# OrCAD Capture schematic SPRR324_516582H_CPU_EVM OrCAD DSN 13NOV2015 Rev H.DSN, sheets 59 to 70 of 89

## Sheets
59 SH66 - ETHERNET LEDS: rev: A
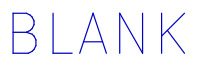
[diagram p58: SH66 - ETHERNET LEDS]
60 SH67 - APPLICATION IF CONN1: size B; rev: A
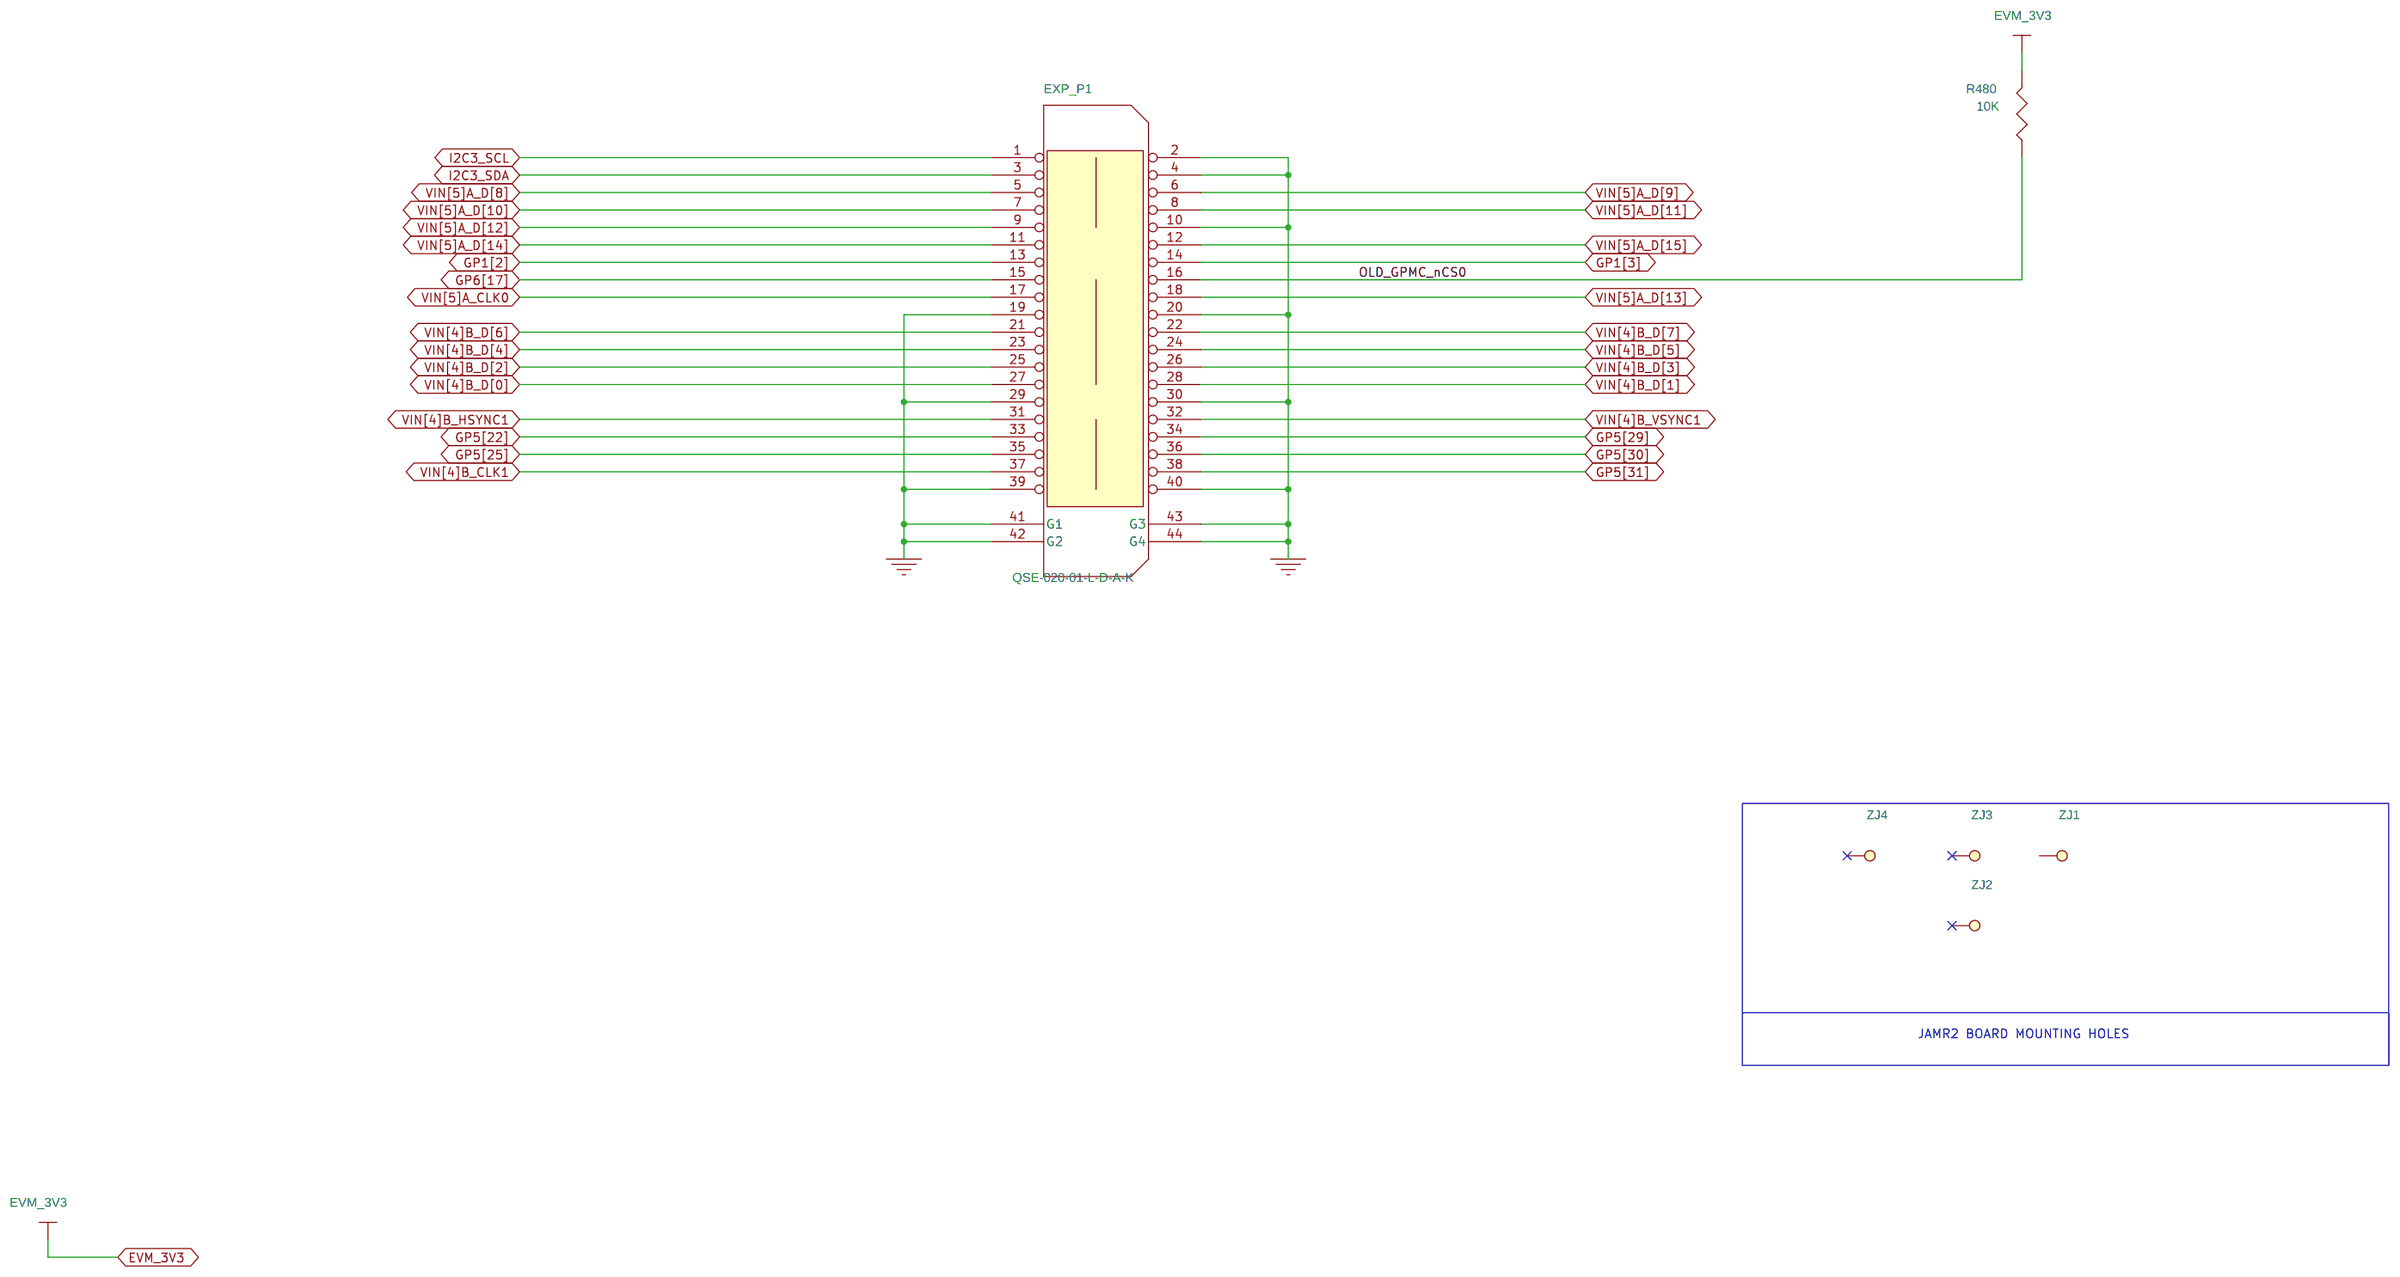
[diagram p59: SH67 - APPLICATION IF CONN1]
61 SH68 - APPLICATION IF  CONN2: size B; rev: A
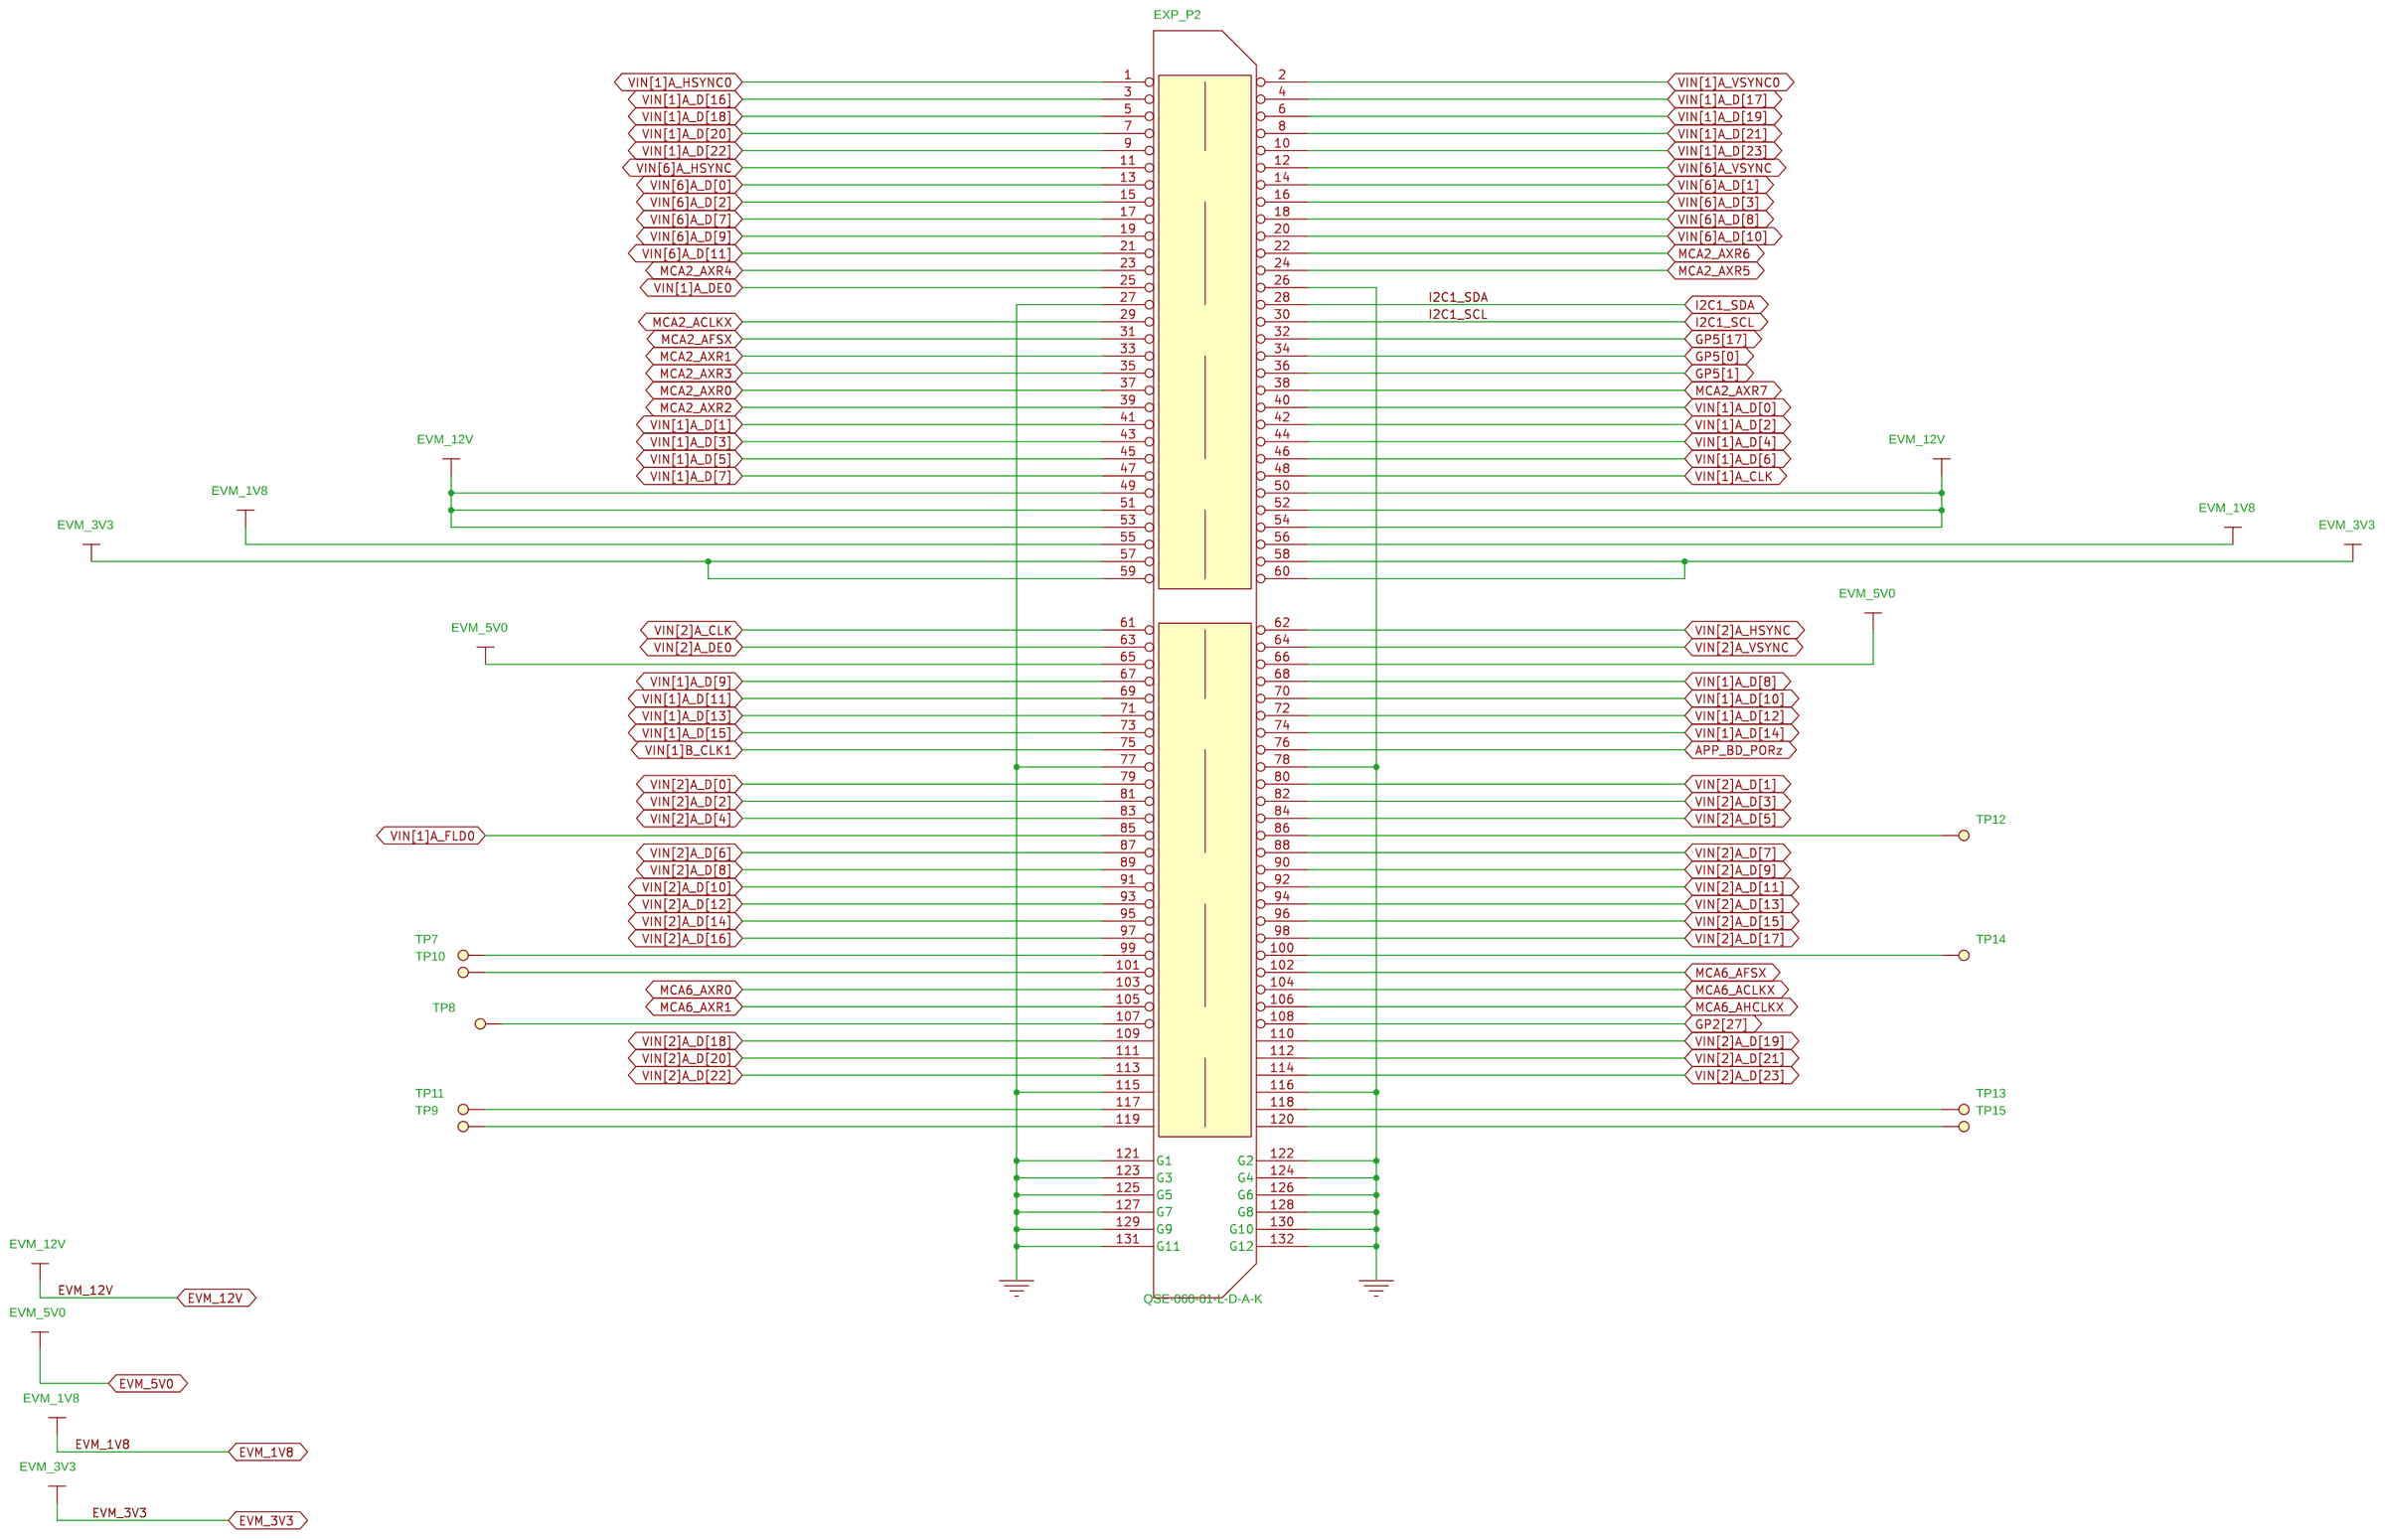
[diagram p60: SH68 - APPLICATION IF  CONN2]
62 SH69 - APPLICATION IF  CONN3: size B; rev: A
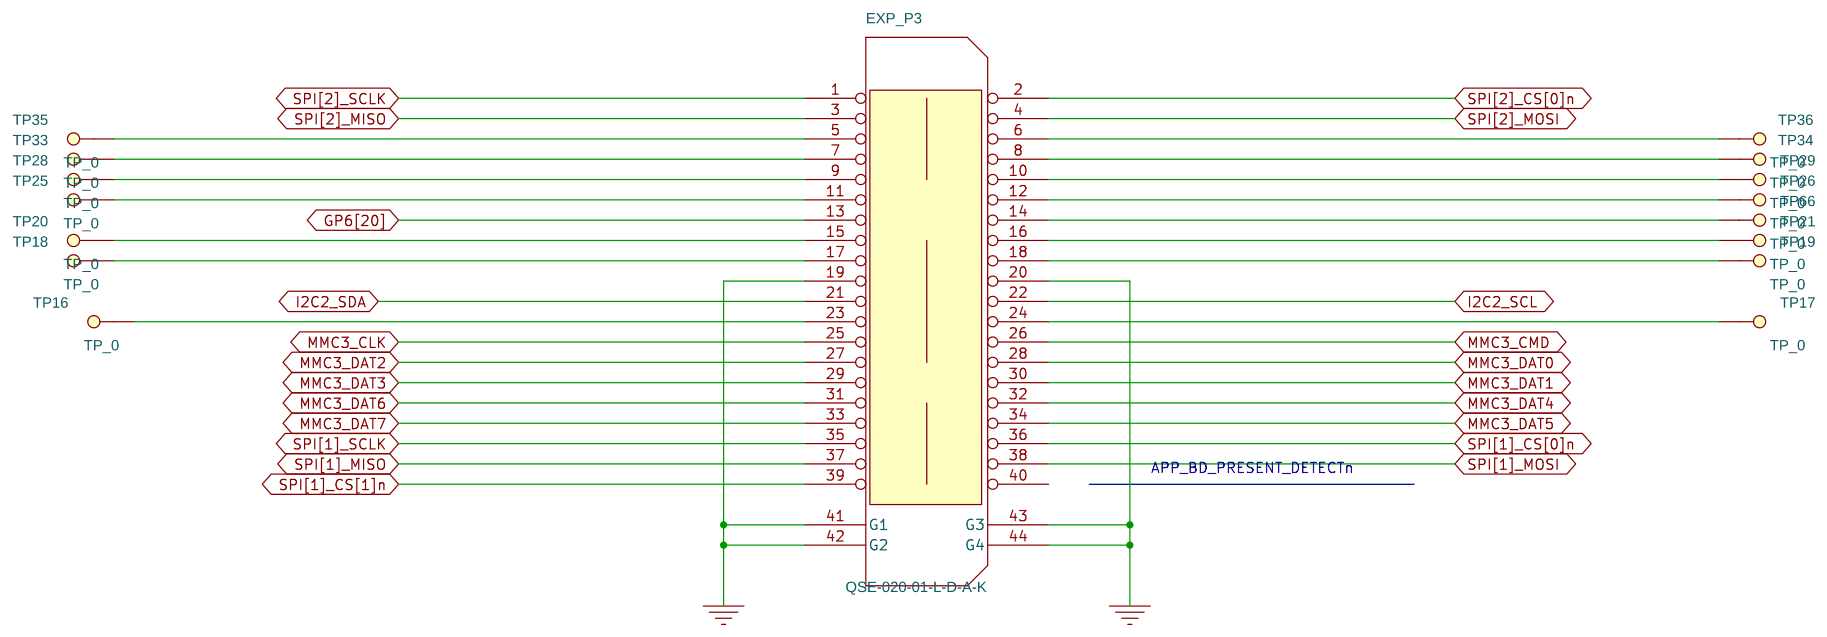
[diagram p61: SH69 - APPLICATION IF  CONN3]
63 SH70 - PMIC CONTROL: size B; rev: G3
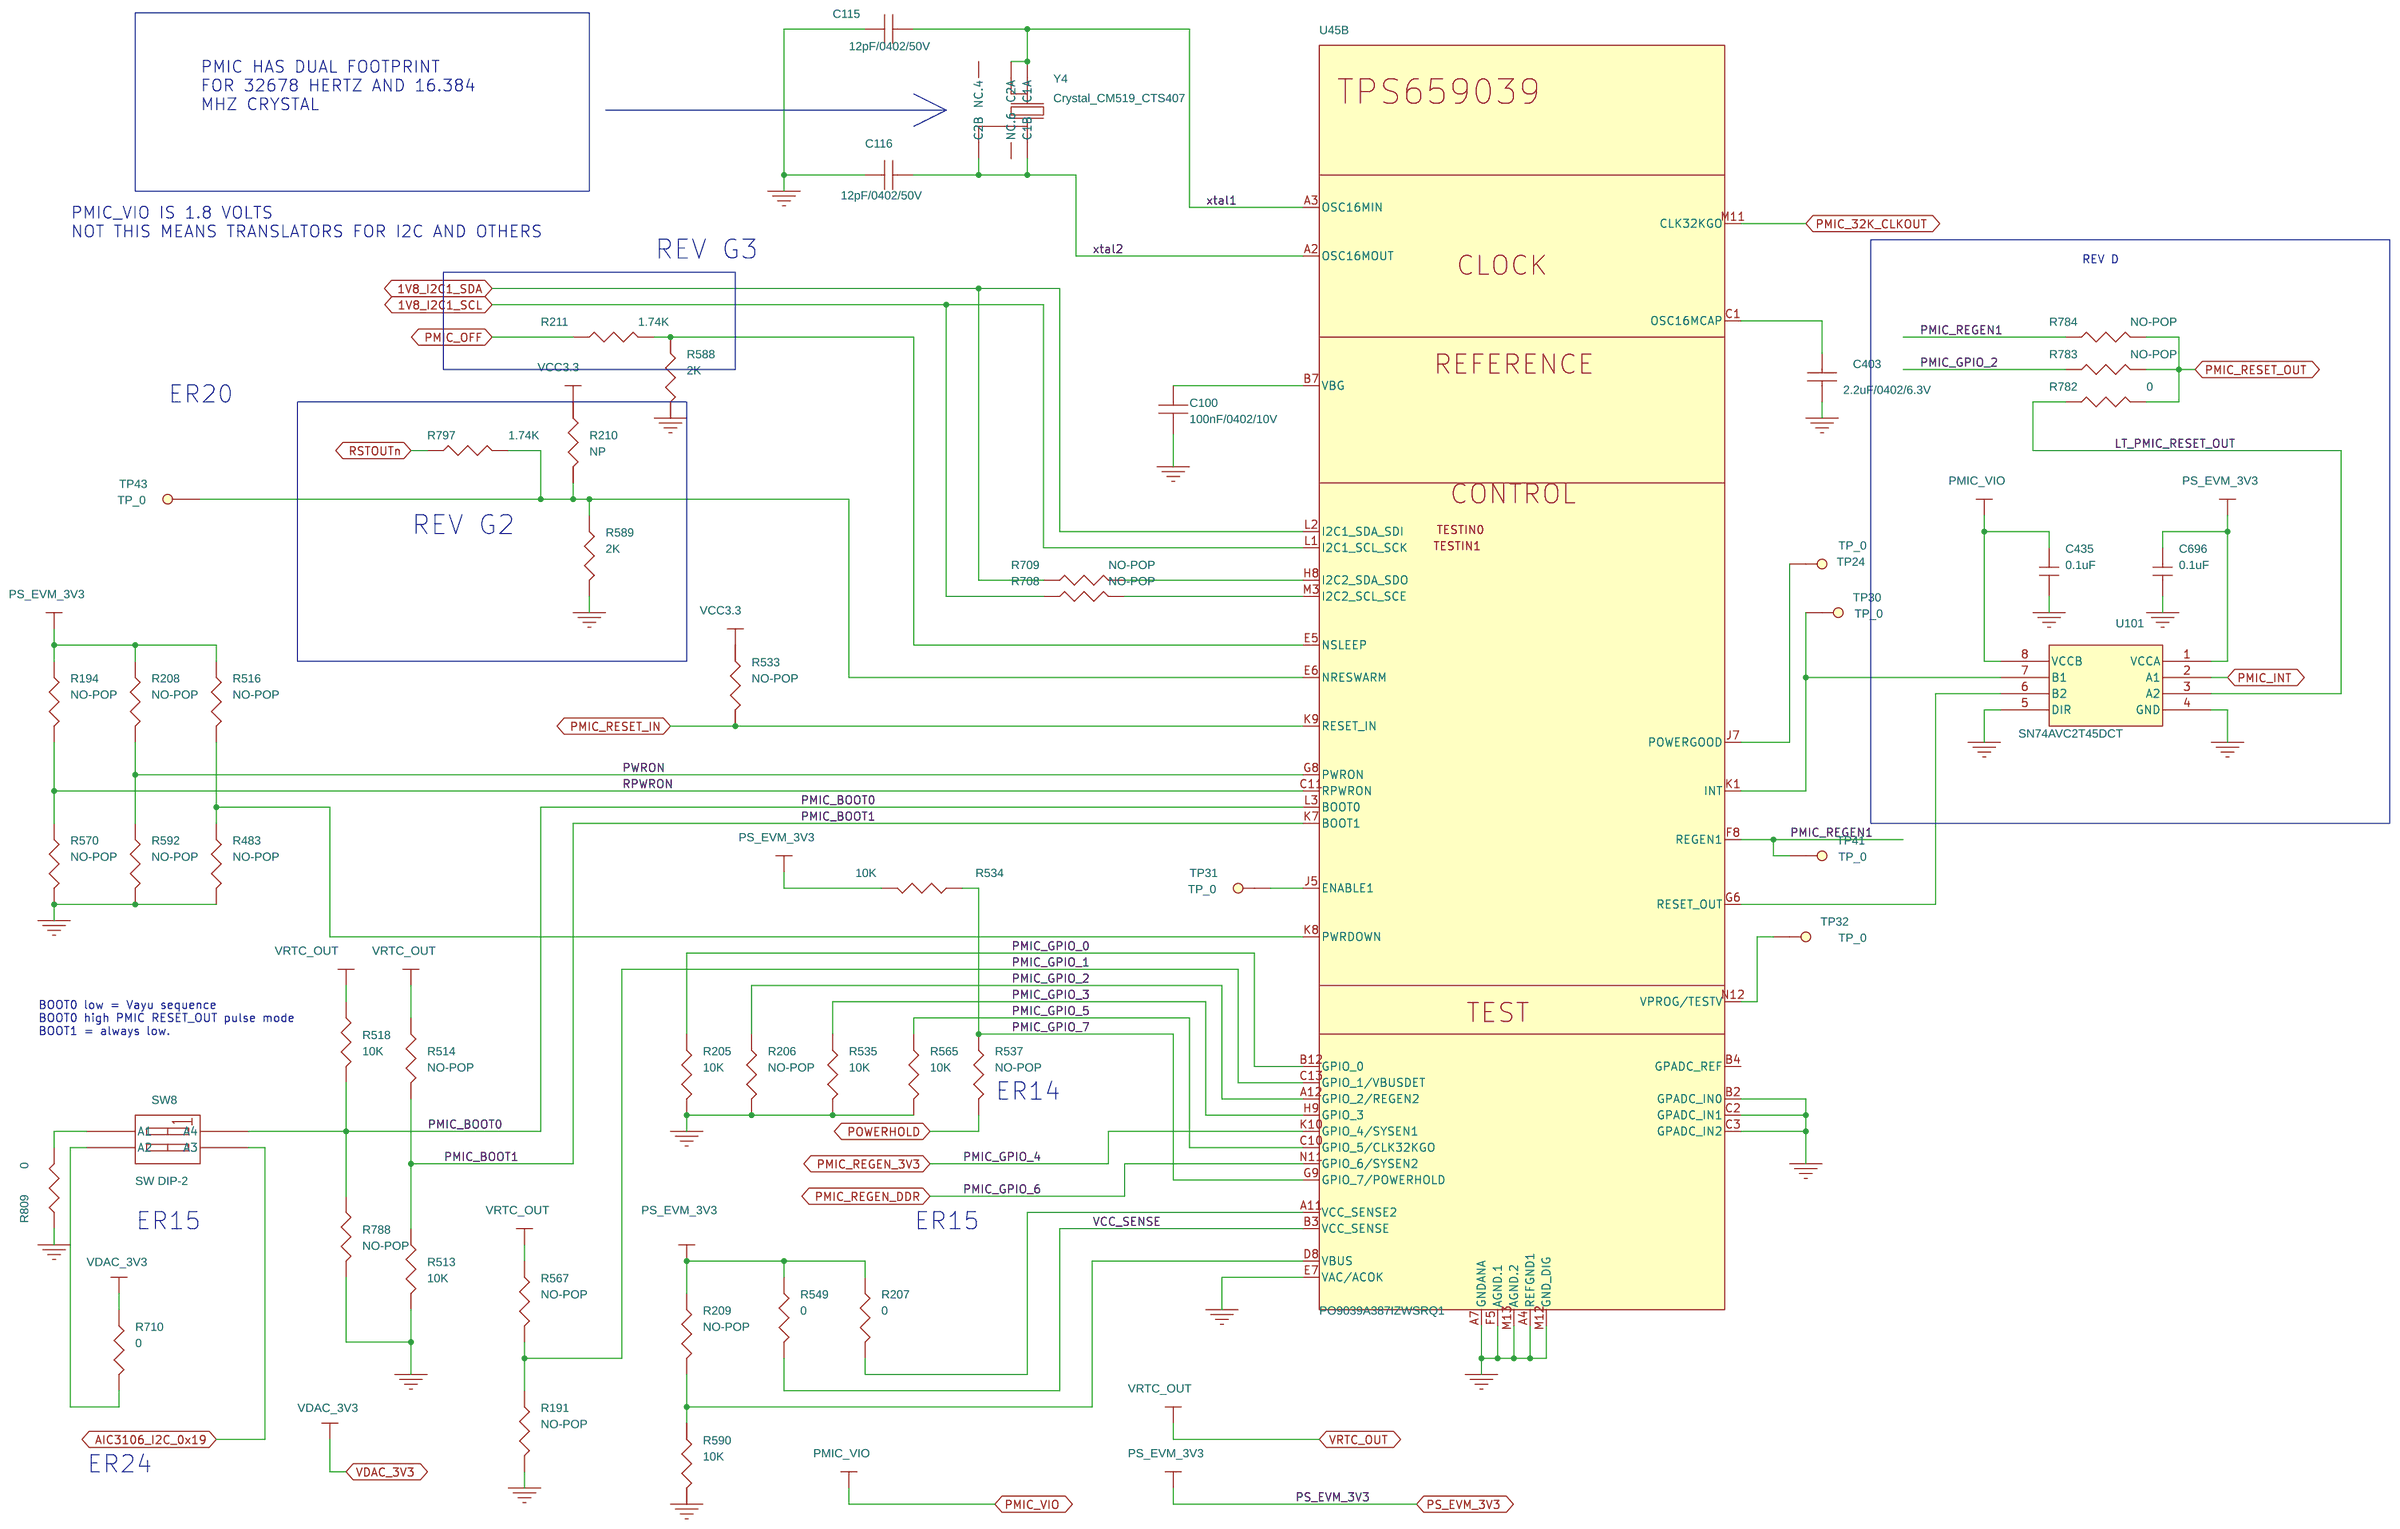
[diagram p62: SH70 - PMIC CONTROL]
64 SH71 - PMIC2: size B
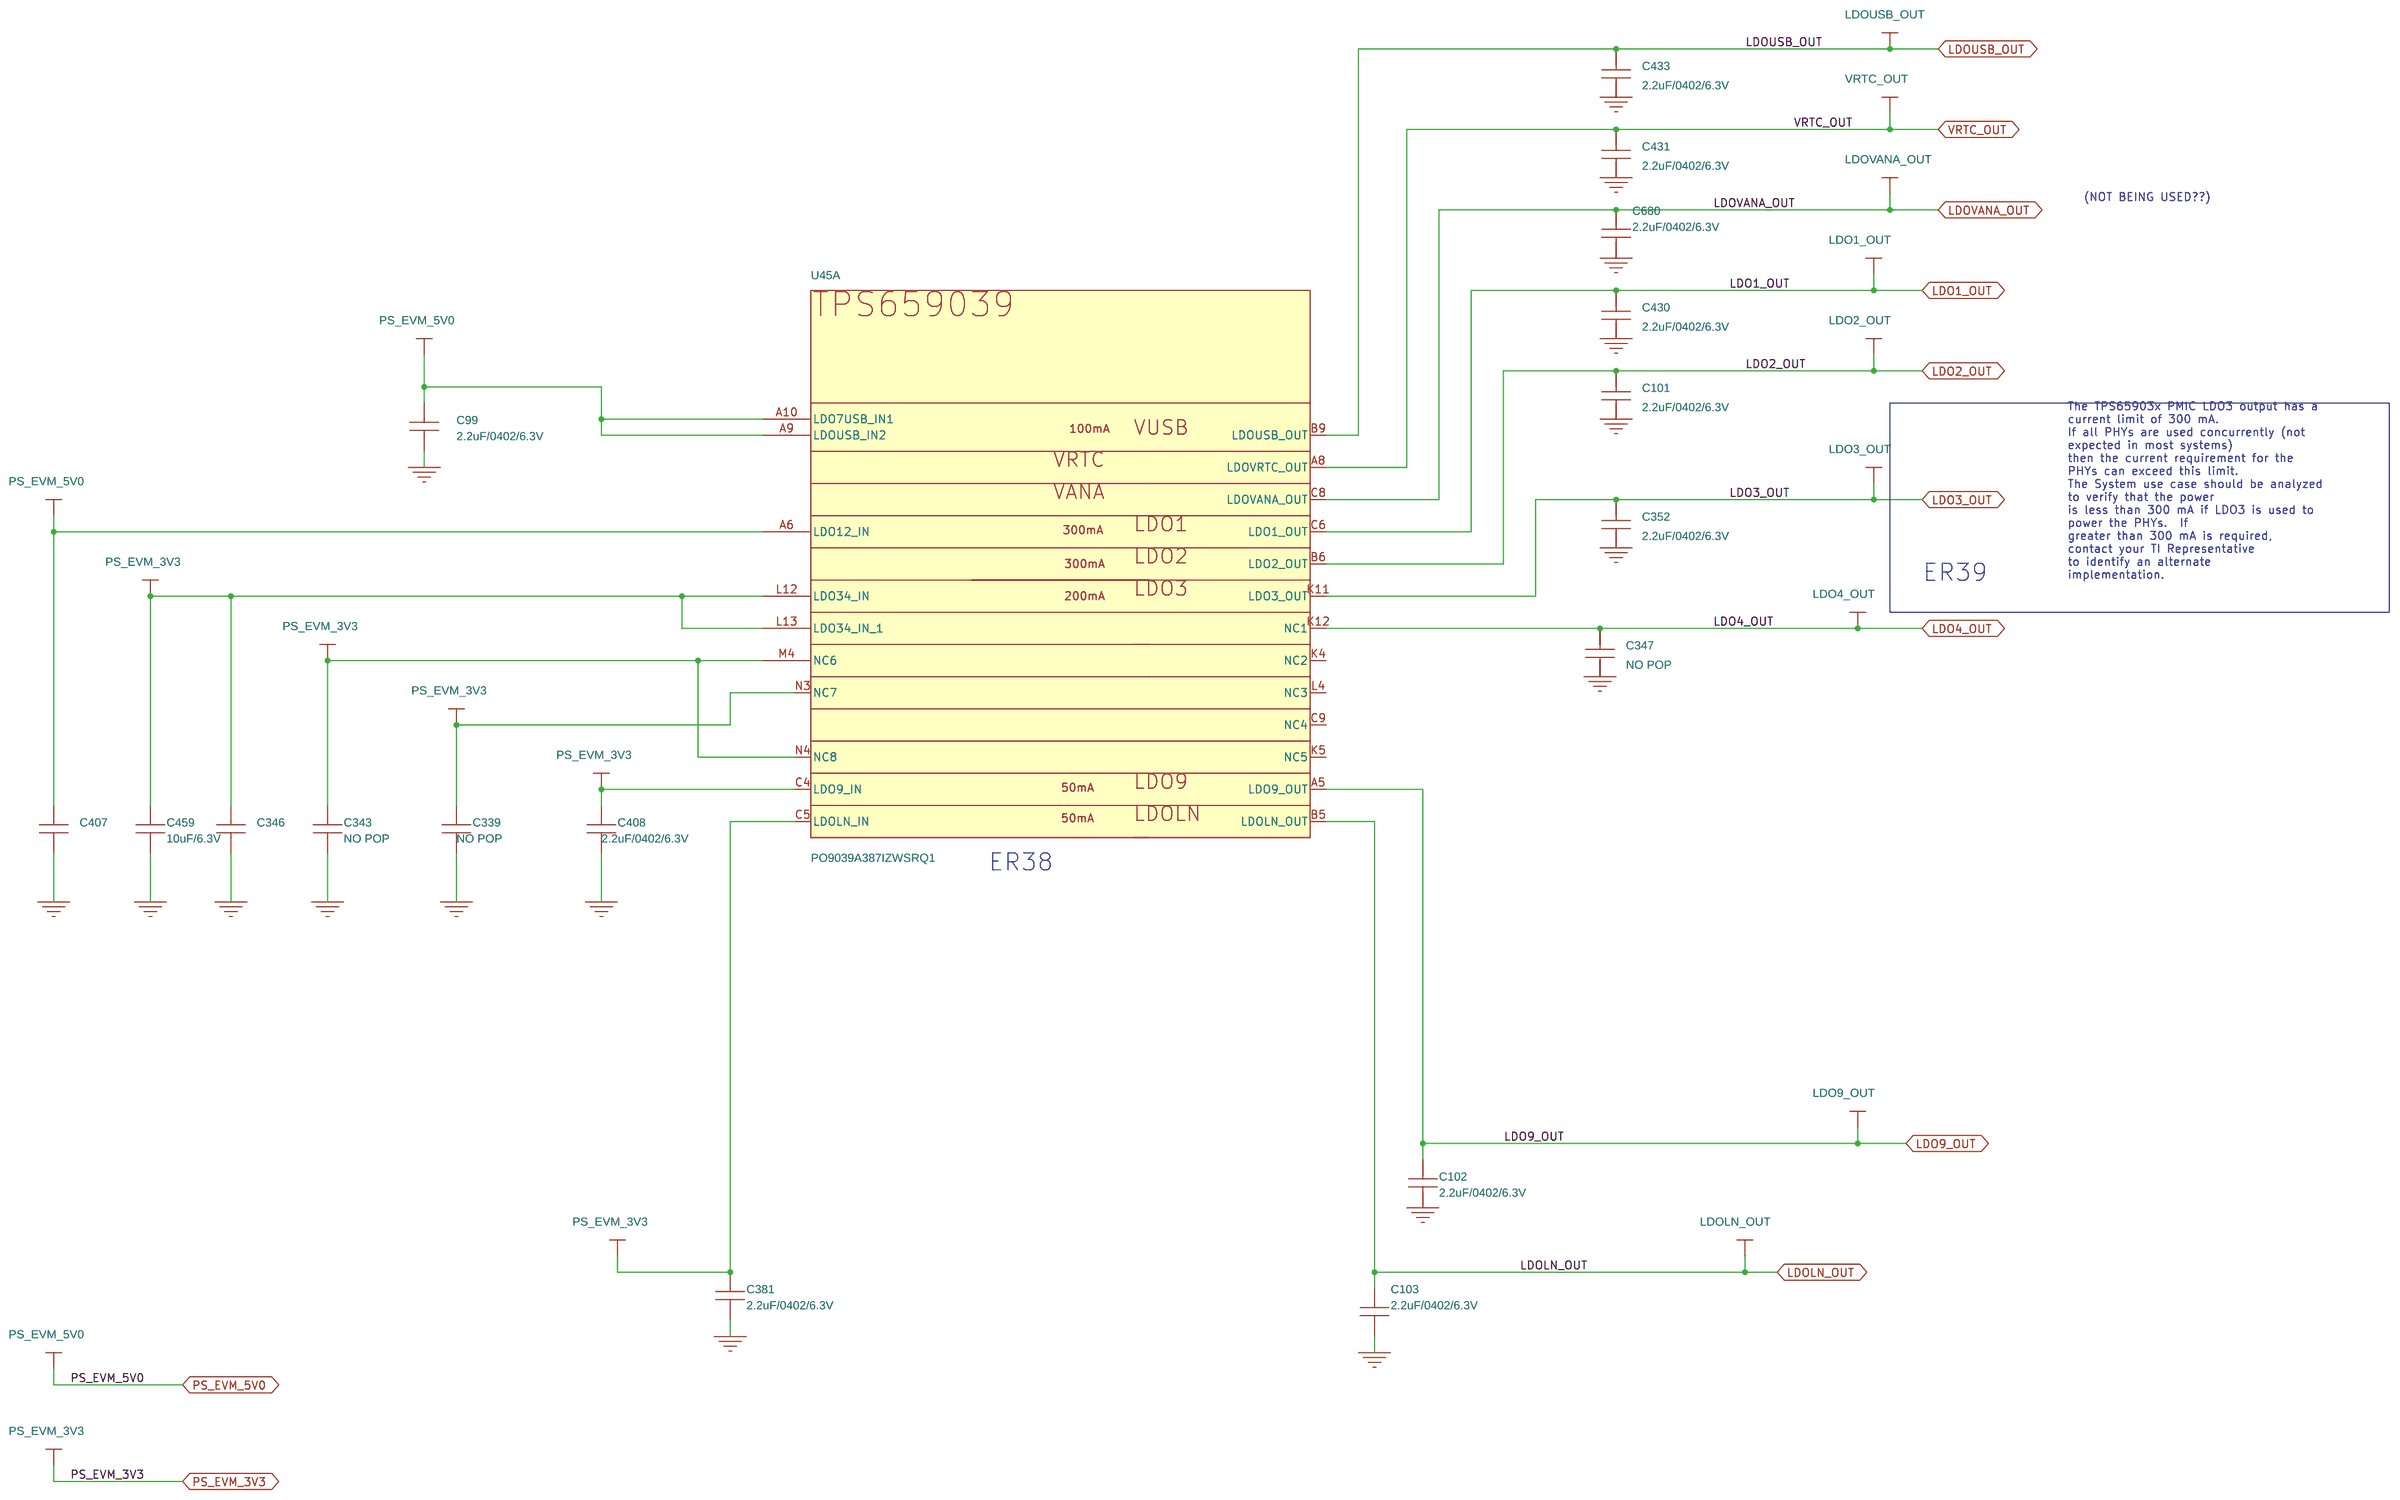
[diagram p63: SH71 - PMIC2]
65 SH72 - PMIC3: size B; rev: D
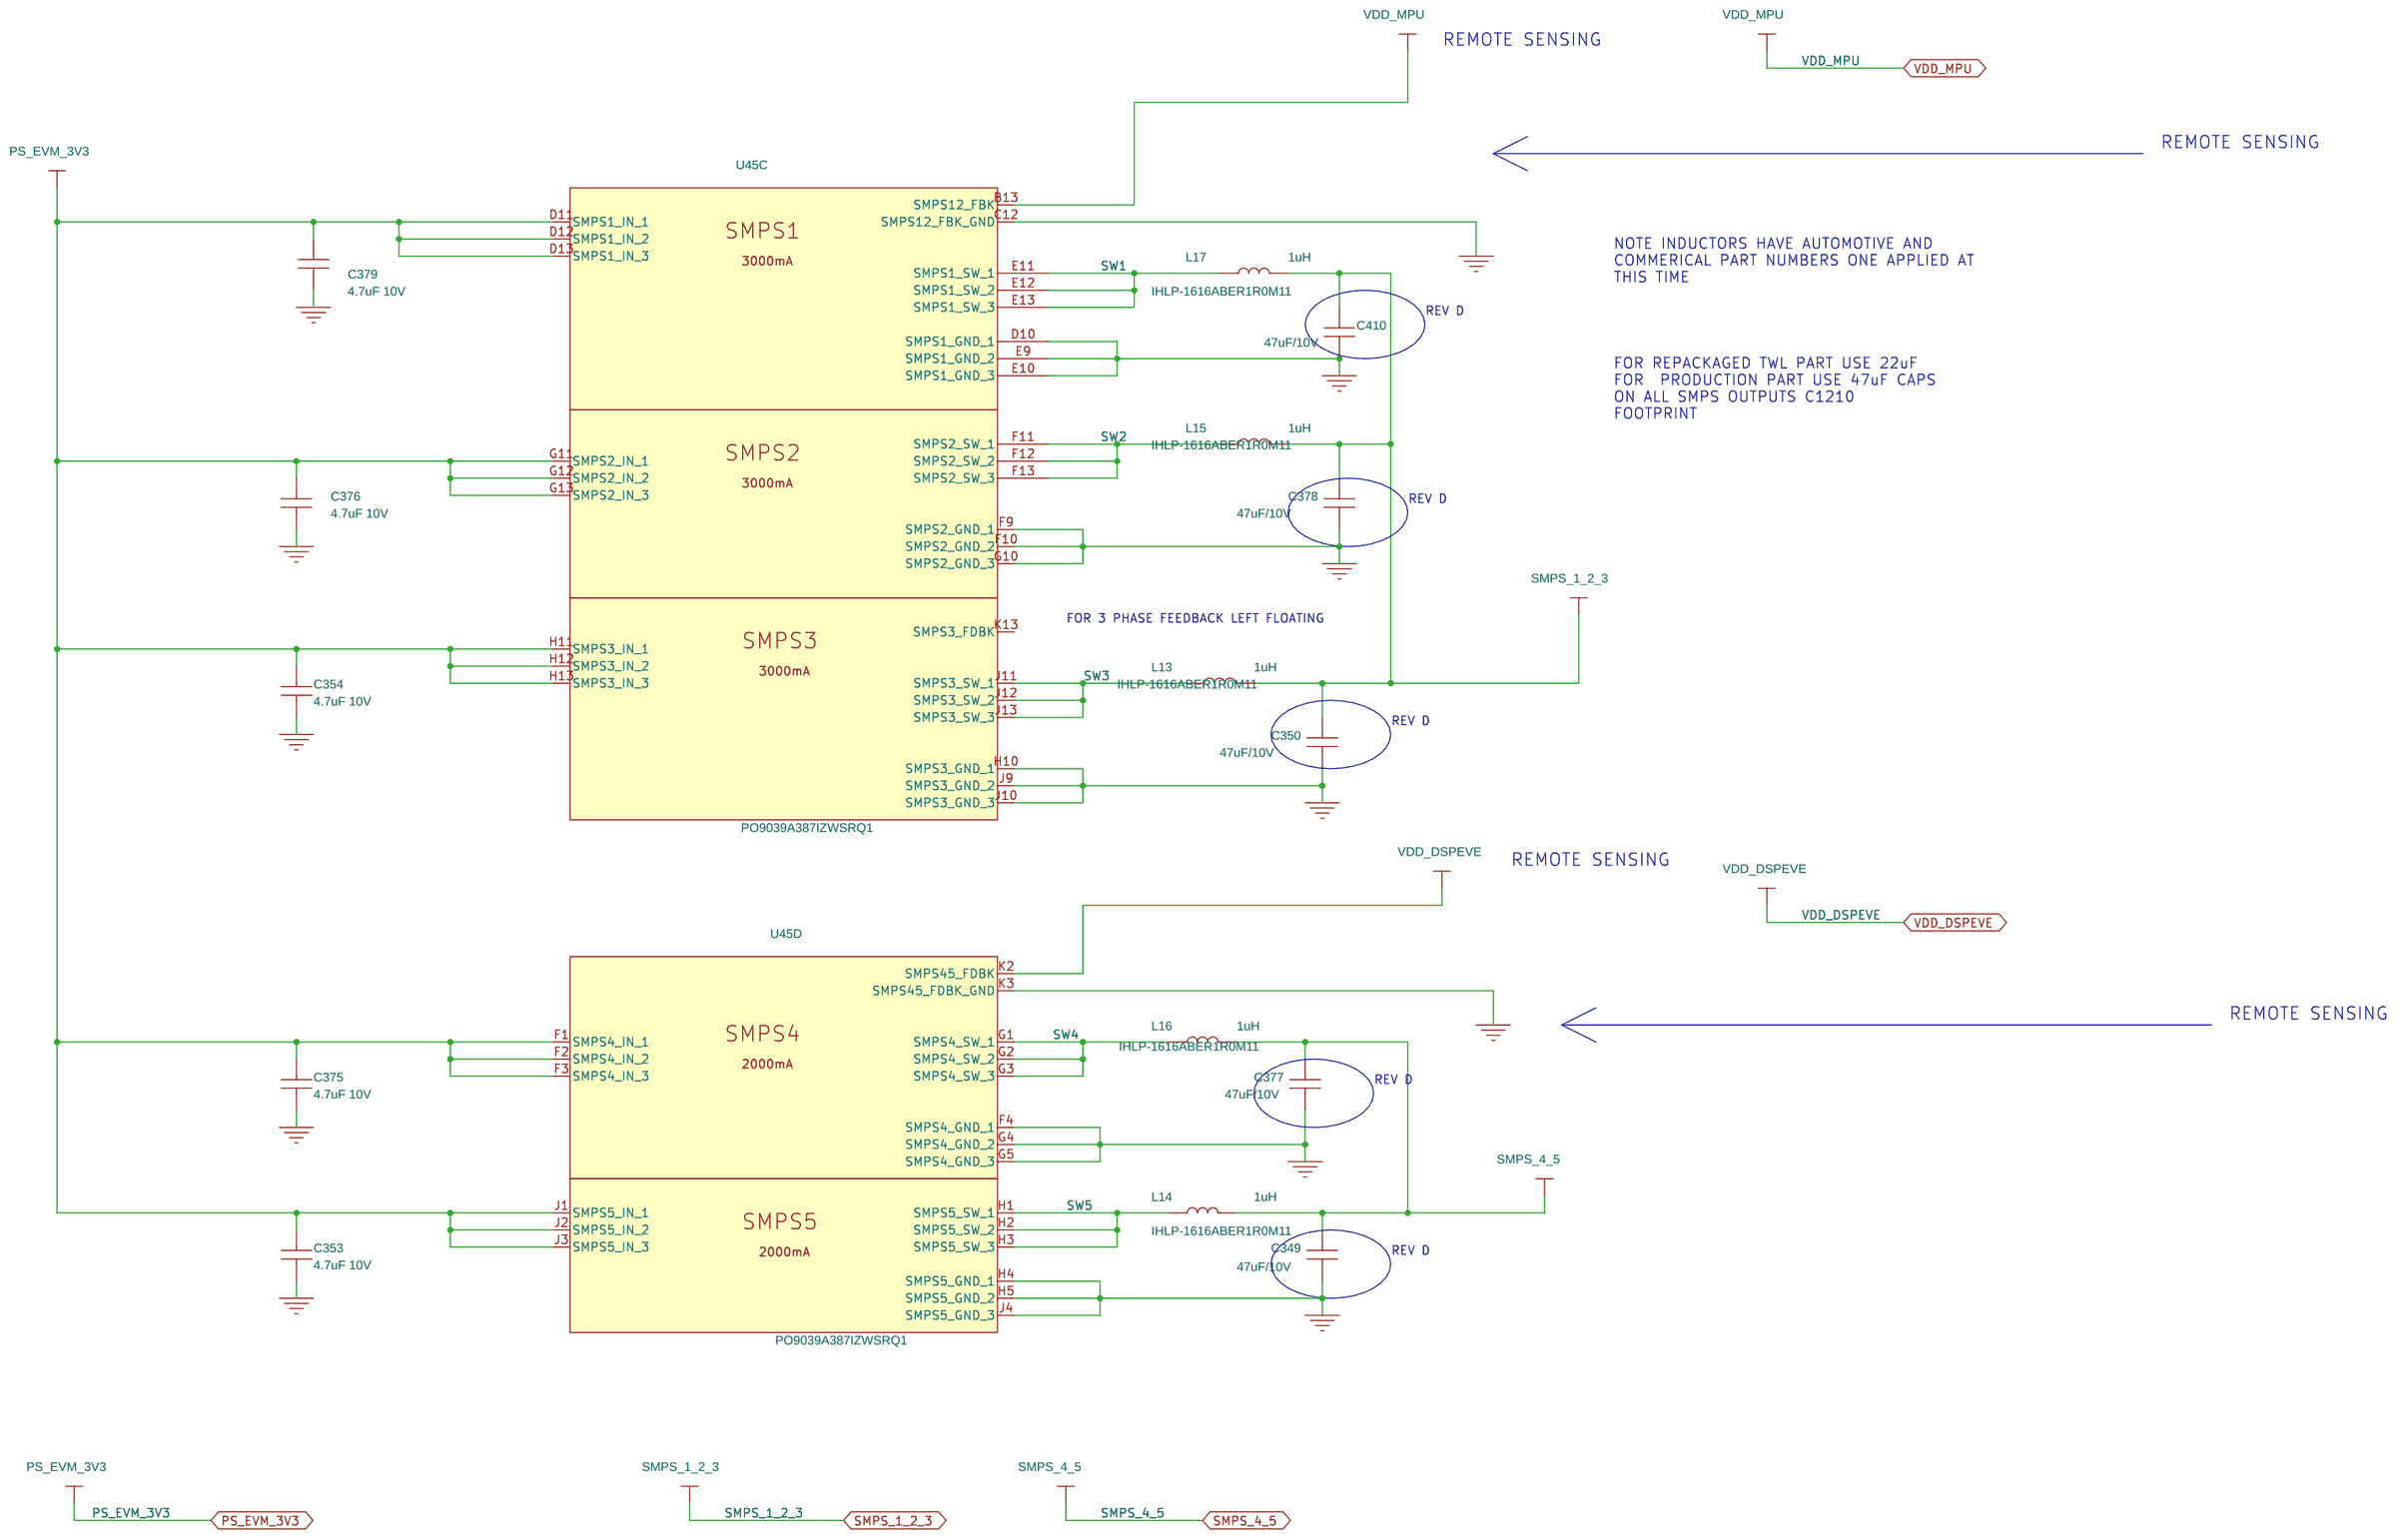
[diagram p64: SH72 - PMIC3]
66 SH73 - PMIC 4: size B; rev: D
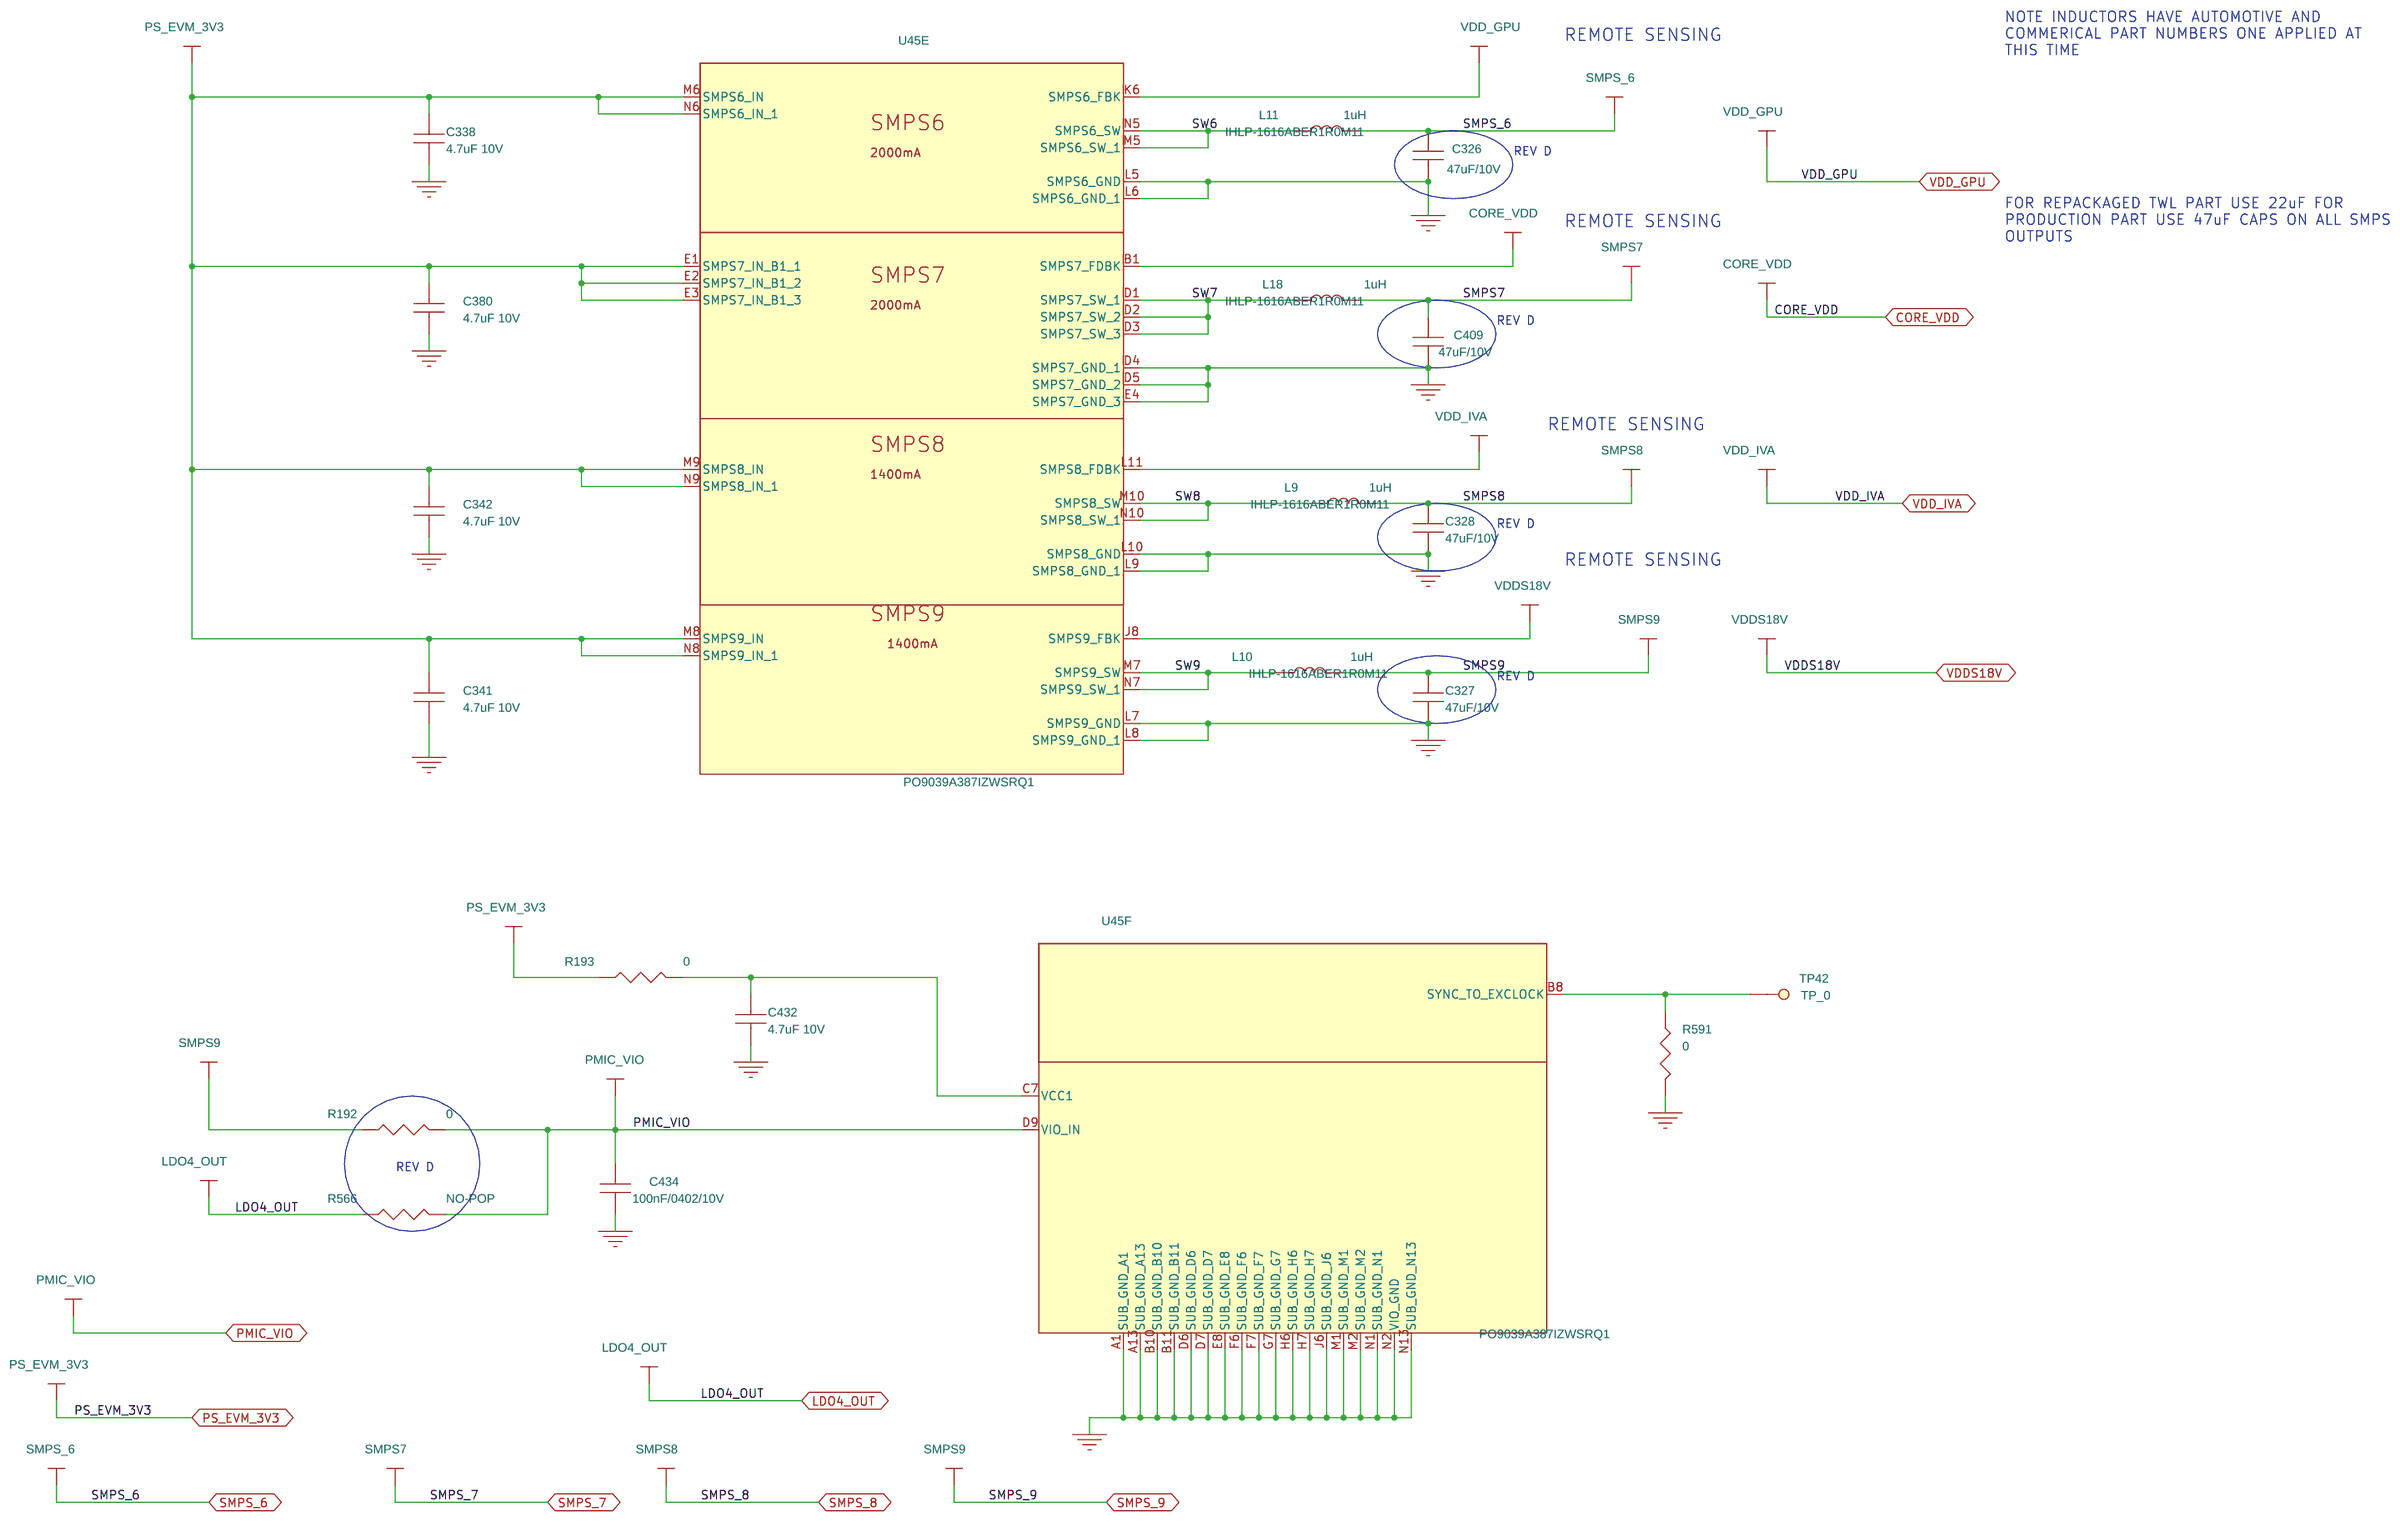
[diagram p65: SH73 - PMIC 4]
67 SH74 - POWER TPS443351DAP: size B
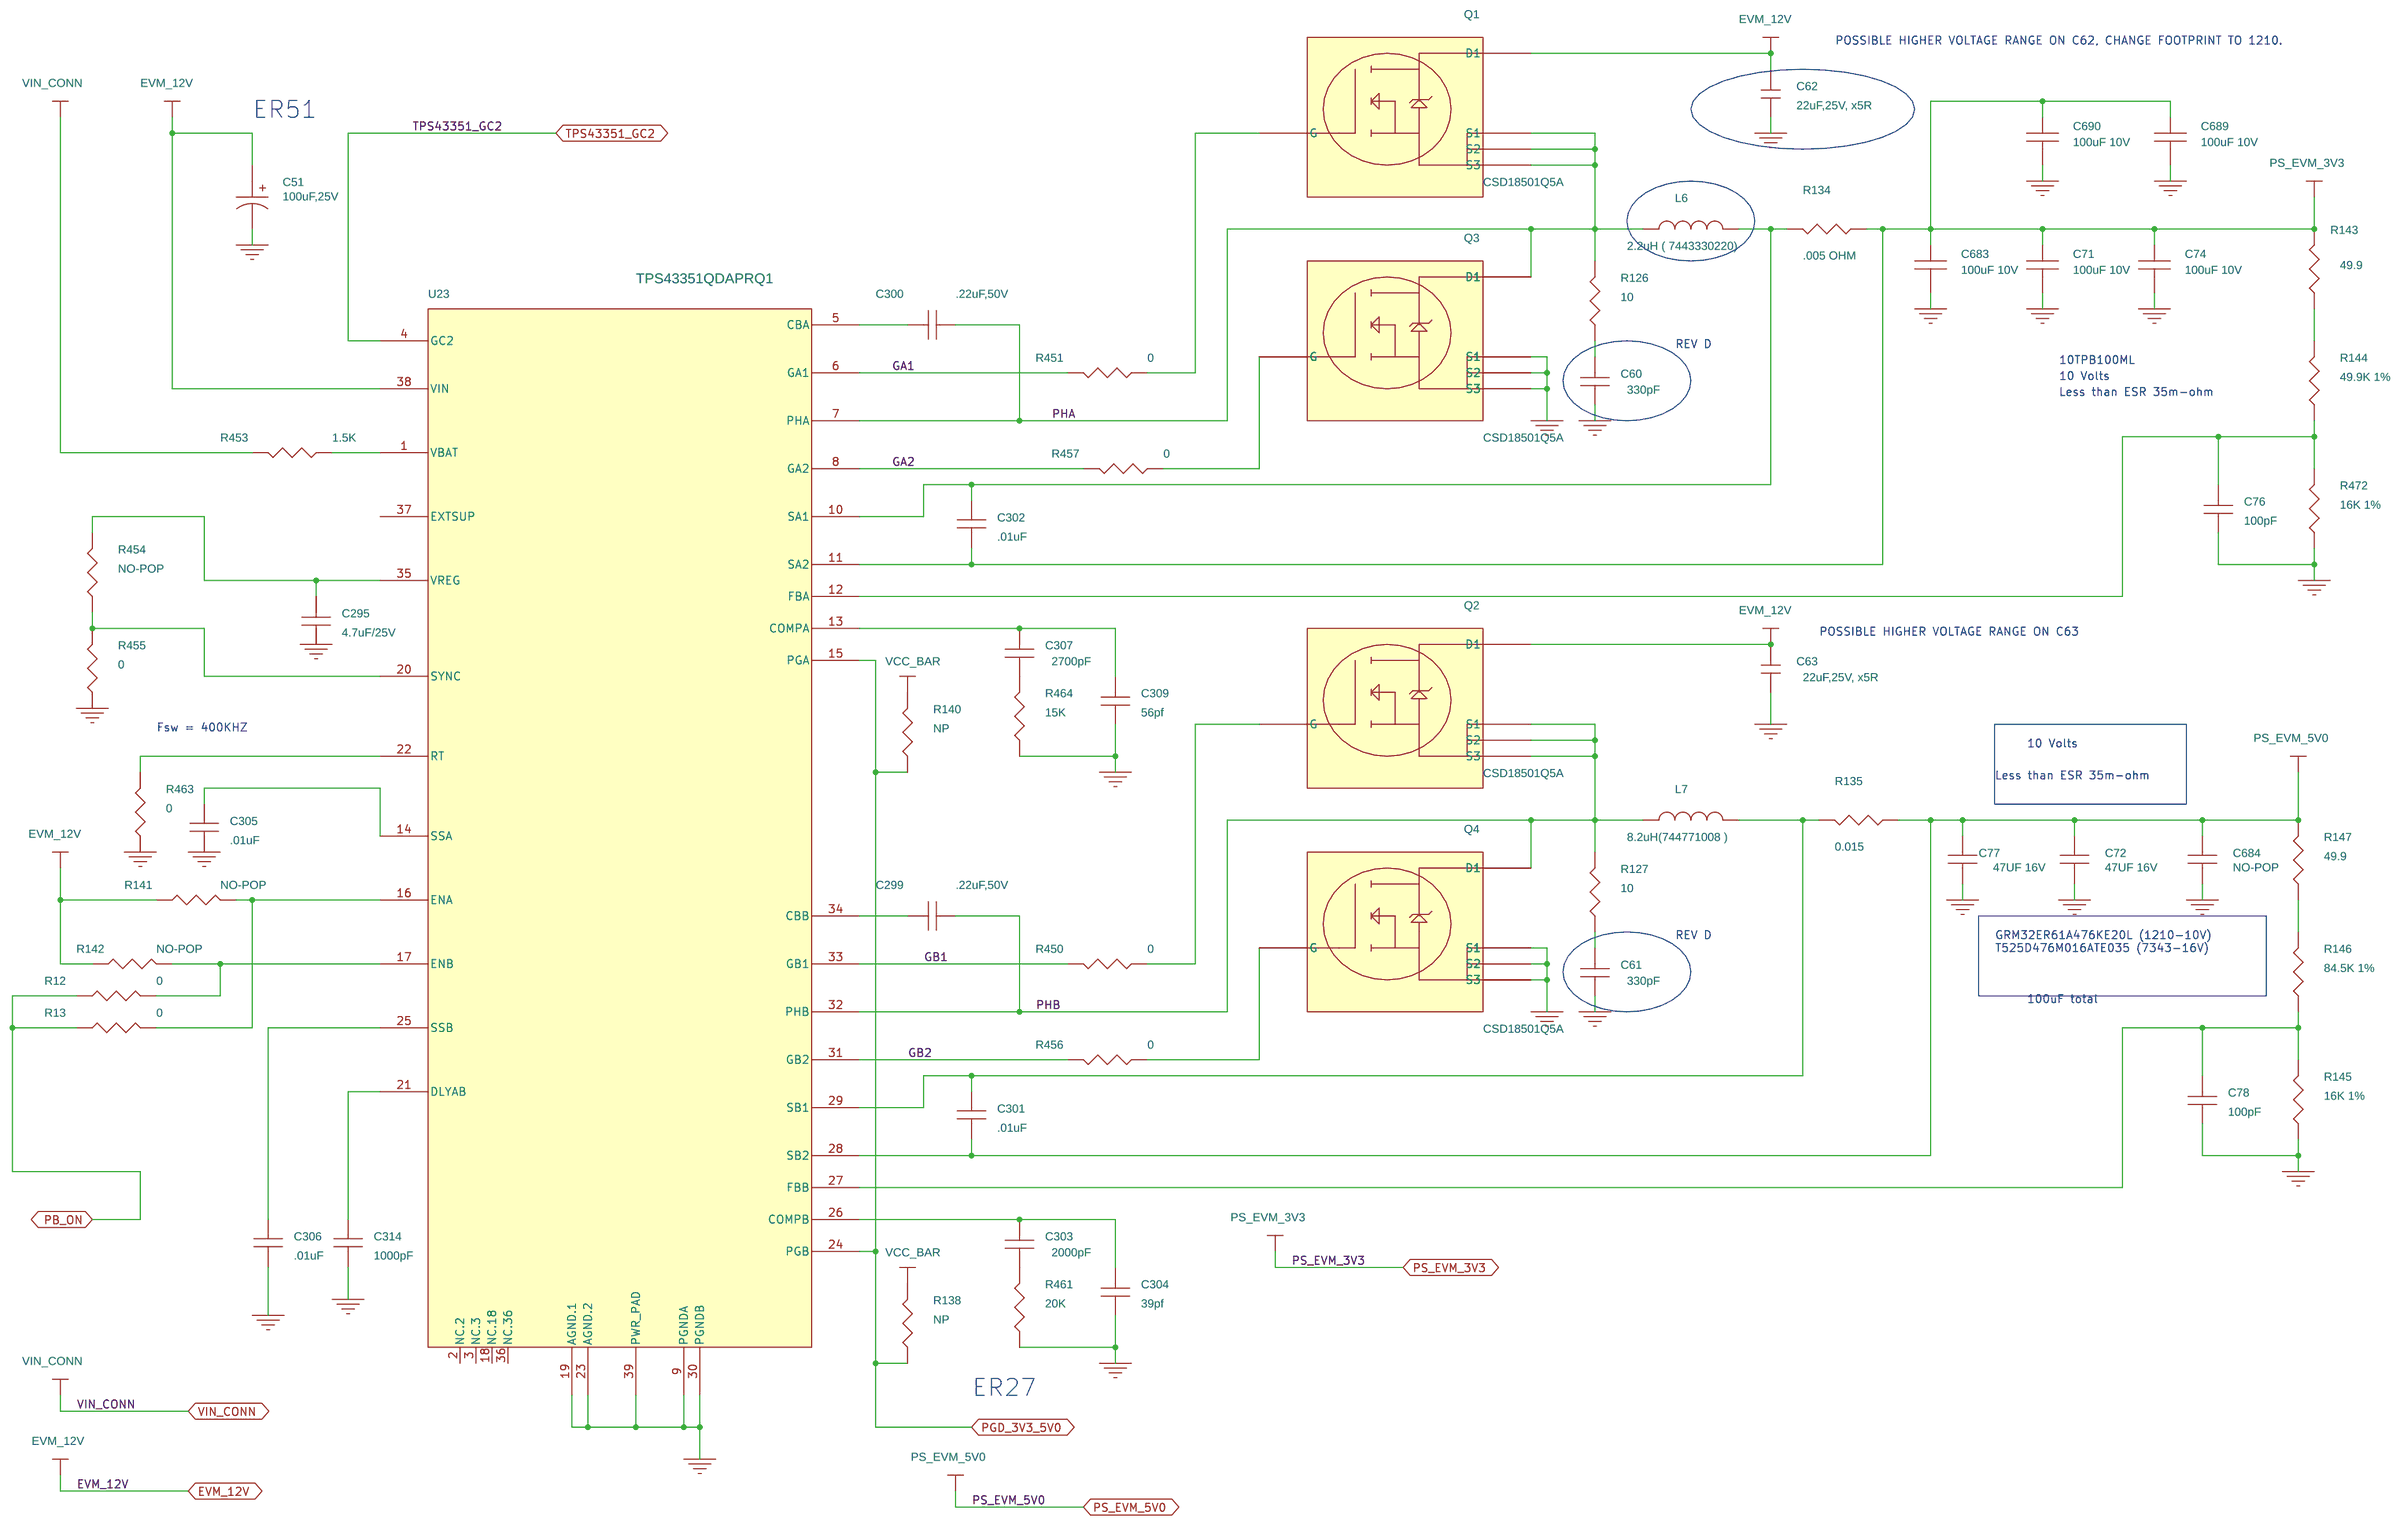
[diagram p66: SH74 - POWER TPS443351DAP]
68 SH75 - TPS22965: size B; rev: A
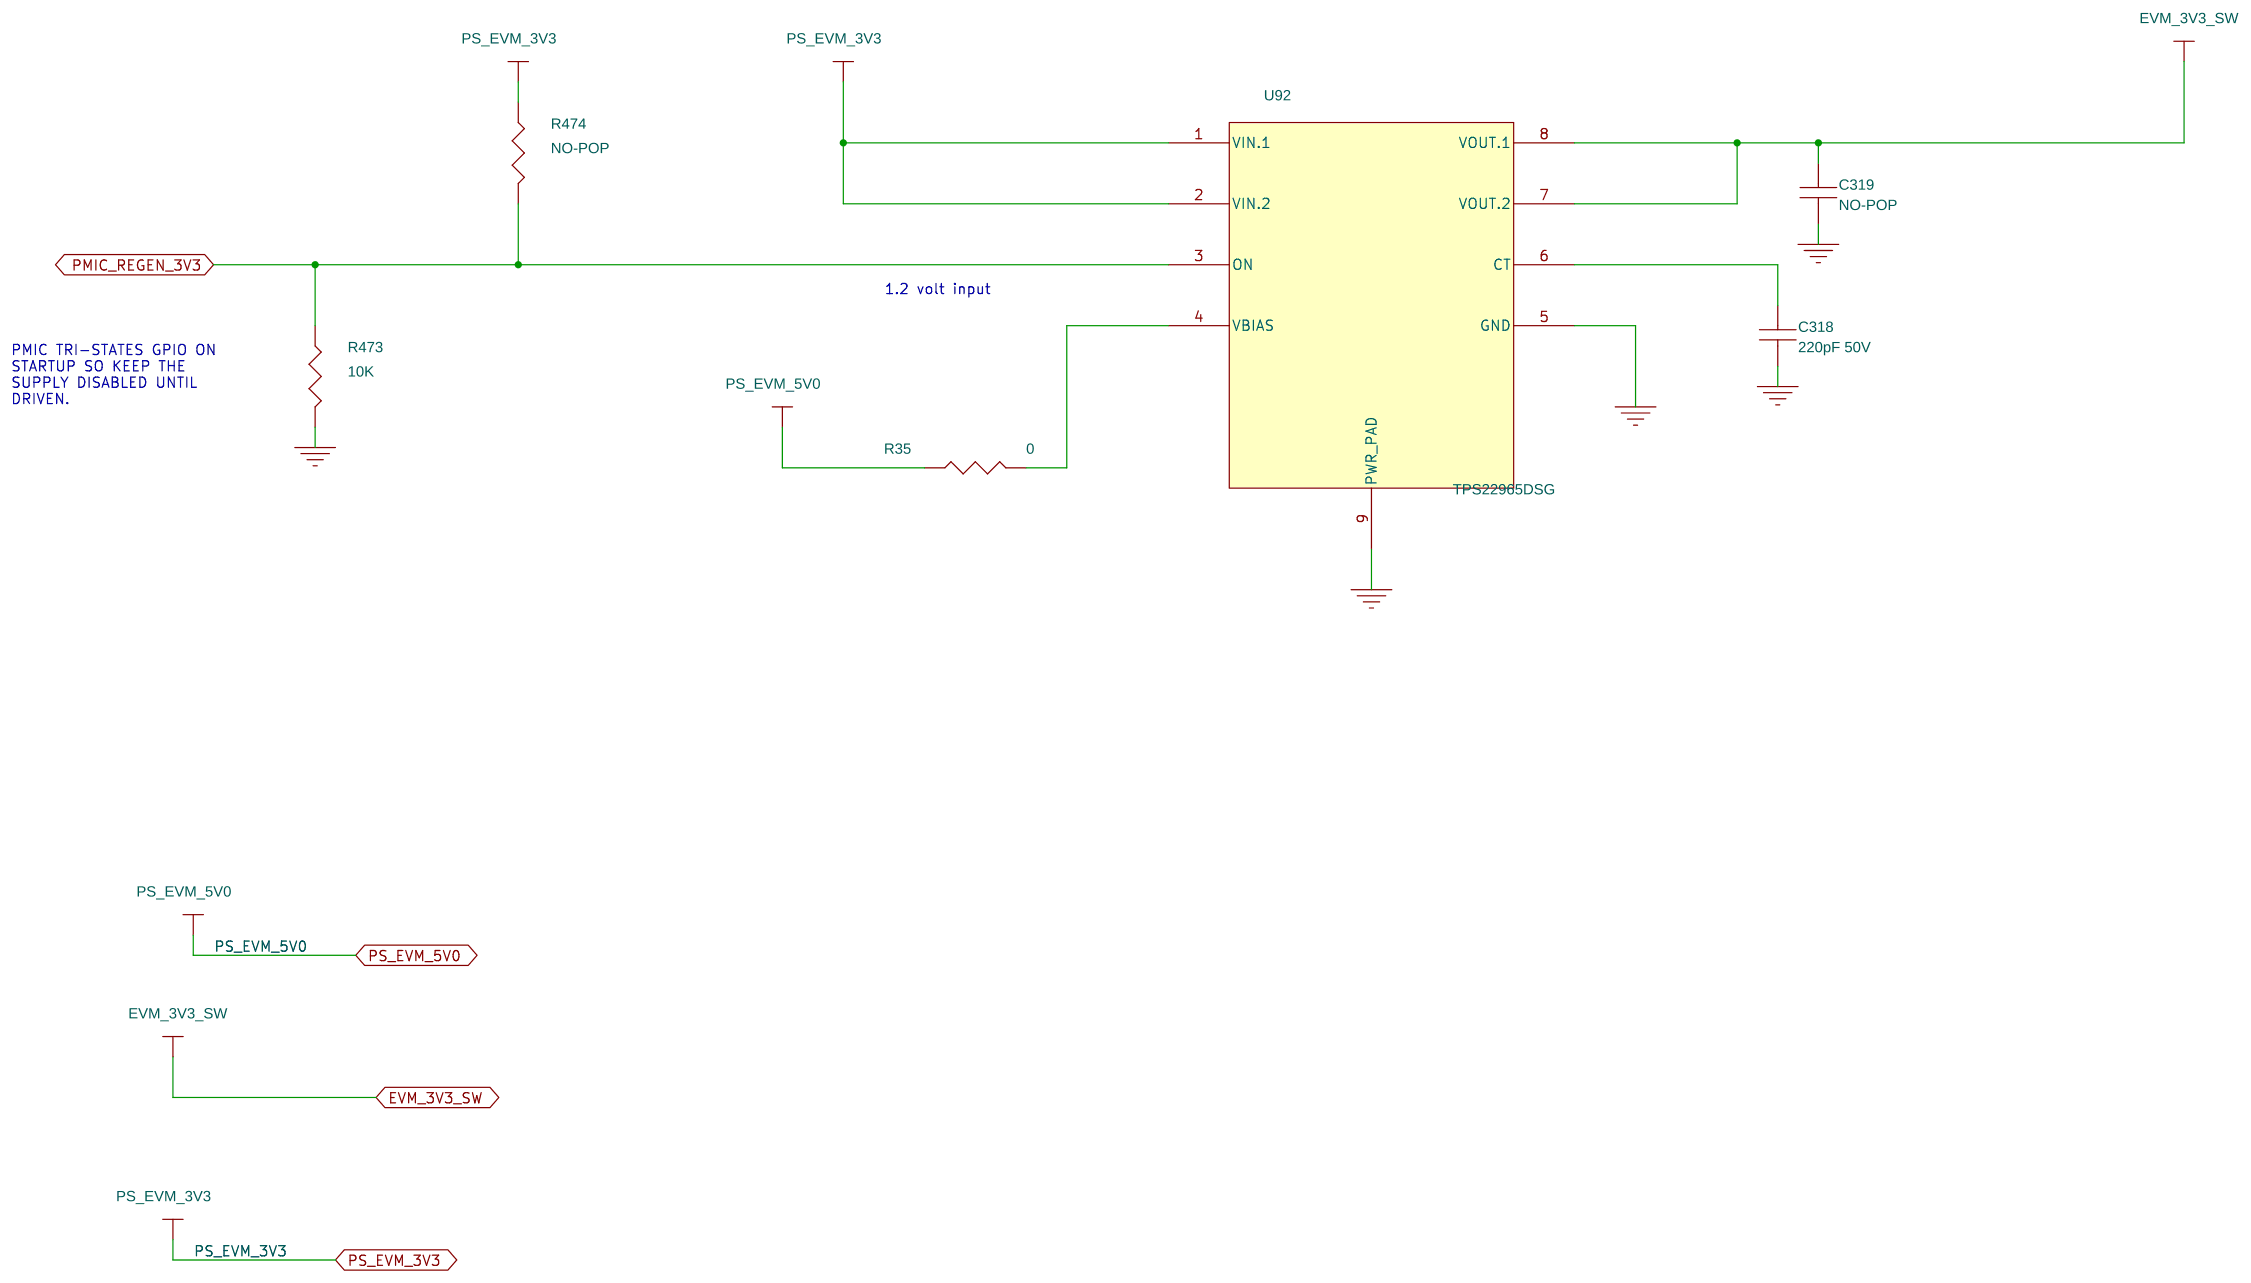
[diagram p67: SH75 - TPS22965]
69 SH76 - ETHERNET 2V5: size B
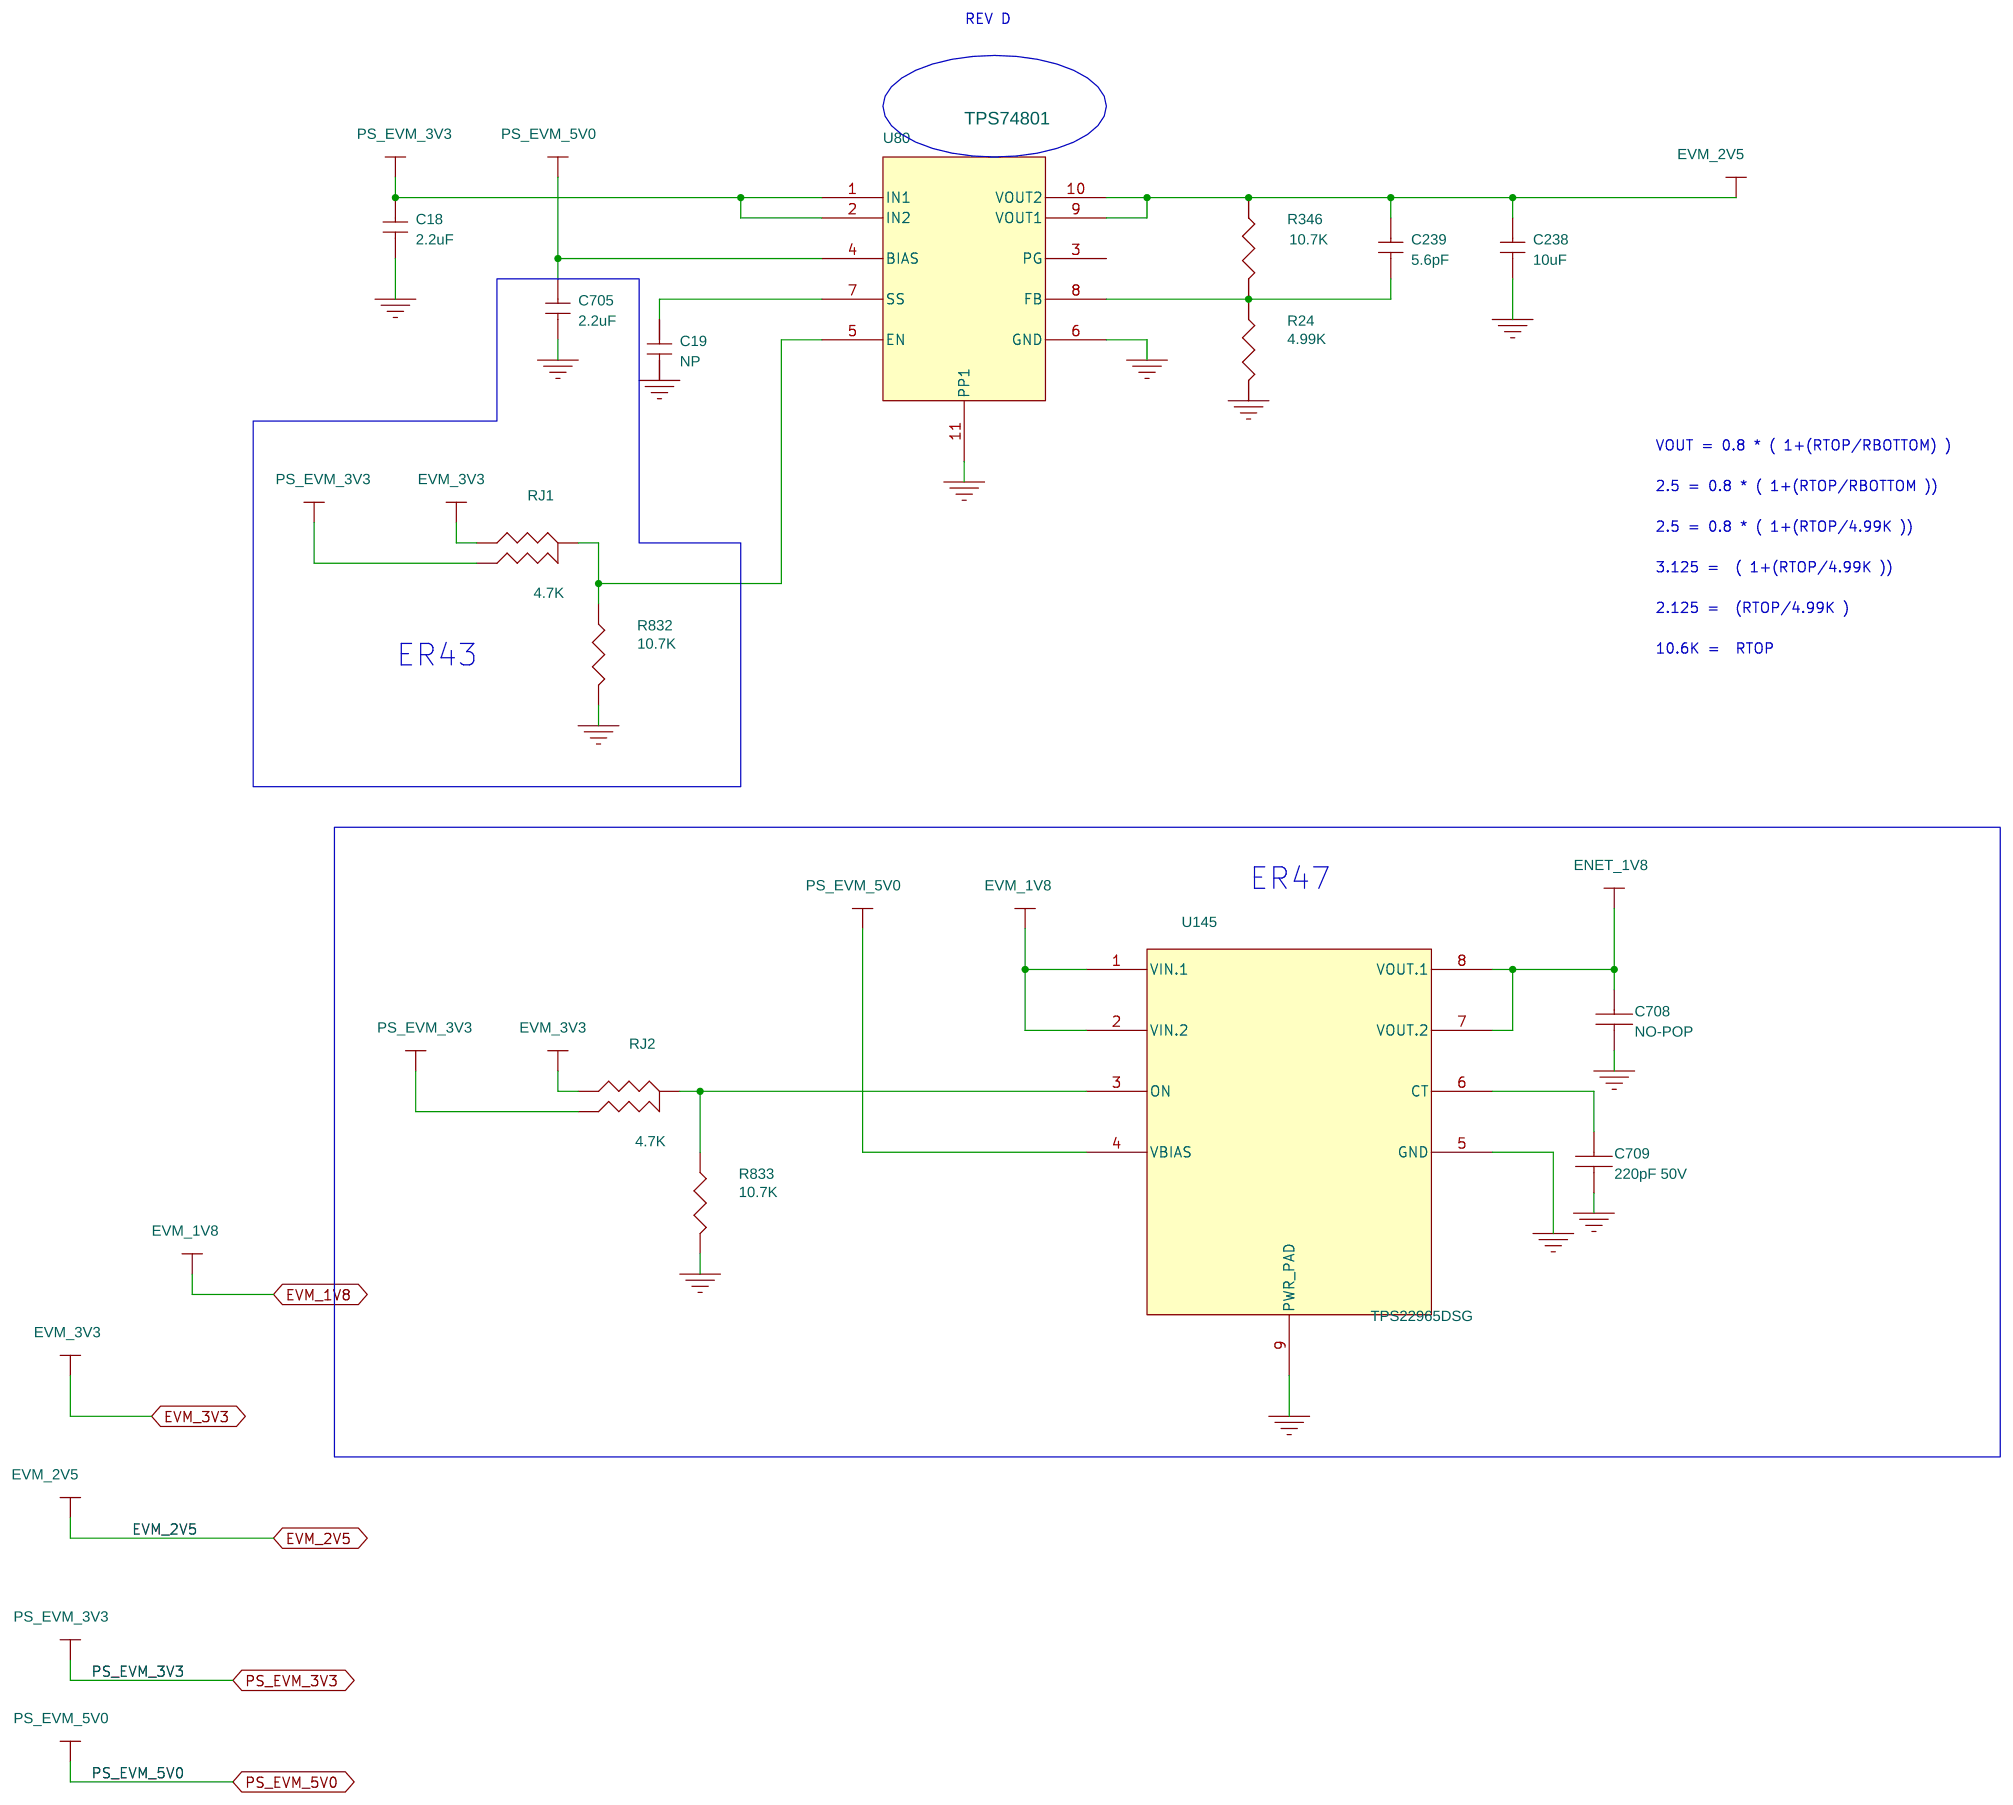
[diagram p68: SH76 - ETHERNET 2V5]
70 SH77 - TPS51200: size B; rev: G
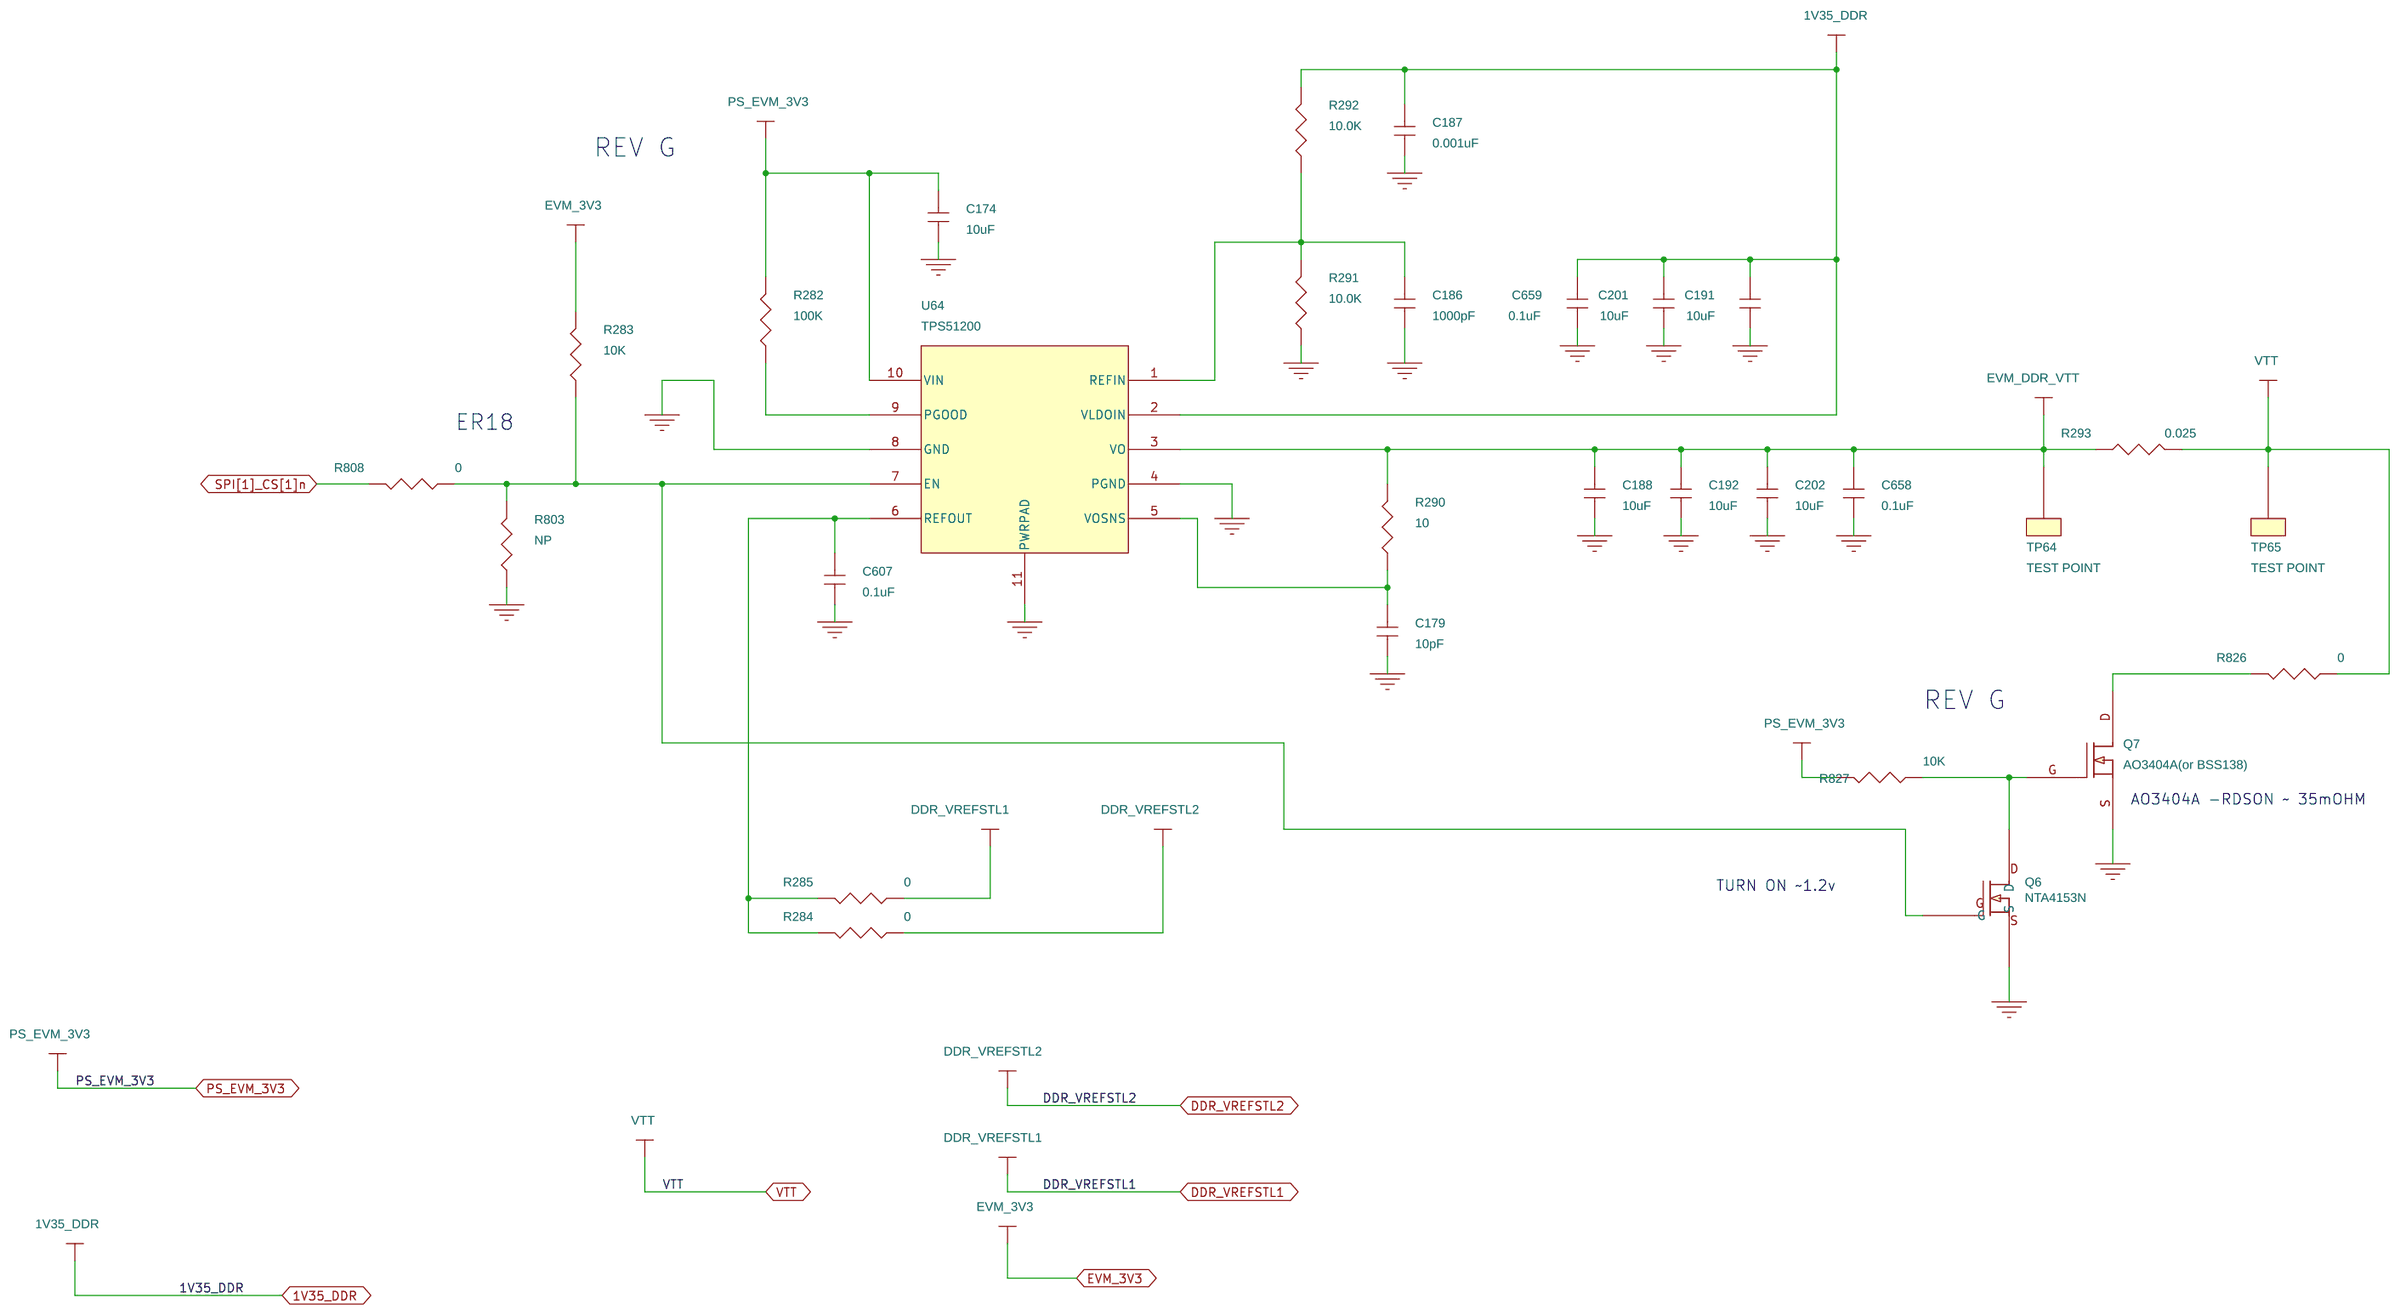
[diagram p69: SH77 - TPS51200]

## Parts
sheet SH67 - APPLICATION IF CONN1
EXP_P1  QSE-020-01-L-D-A-K  [QSE_020]
R480  10K  [r402-25]
ZJ1  TestPoint1_0  [mhp125-250]
ZJ2  MNTHOLE  [mhp125-250]
ZJ3  MNTHOLE  [mhp125-250]
ZJ4  MNTHOLE  [mhp125-250]
sheet SH68 - APPLICATION IF  CONN2
EXP_P2  QSE-060-01-L-D-A-K  [qse-060-0x-x-d-a]
TP7  TestPoint1  [tp1-18rd8]
TP8  TestPoint1  [tp1-18rd8]
TP9  TestPoint1  [tp1-18rd8]
TP10  TestPoint1  [tp1-18rd8]
TP11  TestPoint1  [tp1-18rd8]
TP12  TestPoint1  [tp1-18rd8]
TP13  TestPoint1  [tp1-18rd8]
TP14  TestPoint1  [tp1-18rd8]
TP15  TestPoint1  [tp1-18rd8]
sheet SH69 - APPLICATION IF  CONN3
EXP_P3  QSE-020-01-L-D-A-K  [QSE_020]
TP16  TP_0  [tp1-18rd8]
TP17  TP_0  [tp1-18rd8]
TP18  TP_0  [tp1-18rd8]
TP19  TP_0  [tp1-18rd8]
TP20  TP_0  [tp1-18rd8]
TP21  TP_0  [tp1-18rd8]
TP25  TP_0  [tp1-18rd8]
TP26  TP_0  [tp1-18rd8]
TP28  TP_0  [tp1-18rd8]
TP29  TP_0  [tp1-18rd8]
TP33  TP_0  [tp1-18rd8]
TP34  TP_0  [tp1-18rd8]
TP35  TP_0  [tp1-18rd8]
TP36  TP_0  [tp1-18rd8]
TP66  TP_0  [tp1-18rd8]
sheet SH70 - PMIC CONTROL
C100  100nF/0402/10V  [c402-25]
C115  12pF/0402/50V  [c402-25]
C116  12pF/0402/50V  [c402-25]
C403  2.2uF/0402/6.3V  [c402-25]
C435  0.1uF  [c402-25]
C696  0.1uF  [c402-25]
R191  NO-POP  [r402-25]
R194  NO-POP  [r201-6p6spc]
R205  10K  [r201-6p6spc]
R206  NO-POP  [r201-6p6spc]
R207  0  [r201-6p6spc]
R208  NO-POP  [r201-6p6spc]
R209  NO-POP  [r201-6p6spc]
R210  NP  [r201-6p6spc]
R211  1.74K  [r201-6p6spc]
R483  NO-POP  [r201-6p6spc]
R513  10K  [r402-25]
R514  NO-POP  [r402-25]
R516  NO-POP  [r201-6p6spc]
R518  10K  [r402-25]
R533  NO-POP  [r201-6p6spc]
R534  10K  [r201-6p6spc]
R535  10K  [r201-6p6spc]
R537  NO-POP  [r201-6p6spc]
R549  0  [r201-6p6spc]
R565  10K  [r201-6p6spc]
R567  NO-POP  [r402-25]
R570  NO-POP  [r201-6p6spc]
R588  2K  [r201-6p6spc]
R589  2K  [r201-6p6spc]
R590  10K  [r201-6p6spc]
R592  NO-POP  [r201-6p6spc]
R708  NO-POP  [r201-6p6spc]
R709  NO-POP  [r201-6p6spc]
R710  0  [r402-25]
R782  0  [r402-25]
R783  NO-POP  [r402-25]
R784  NO-POP  [r402-25]
R788  NO-POP  [r402-25]
R797  1.74K  [r402-25]
R809  0  [r402-25]
SW8  SW DIP-2  [sw2-30x50-tda]
TP24  TP_0  [tp1-18rd8]
TP30  TP_0  [tp1-18rd8]
TP31  TP_0  [tp1-18rd8]
TP32  TP_0  [tp1-18rd8]
TP41  TP_0  [tp1-18rd8]
TP43  TP_0  [tp1-18rd8]
U101  SN74AVC2T45DCT  [dct8-14x70]
Y4  Crystal_CM519_CTS407  [xtal2-cm519-dual-cts407]
sheet SH71 - PMIC2
C99  2.2uF/0402/6.3V  [c402-25]
C101  2.2uF/0402/6.3V  [c402-25]
C102  2.2uF/0402/6.3V  [c402-25]
C103  2.2uF/0402/6.3V  [c402-25]
C339  NO POP  [c402-25]
C343  NO POP  [c402-25]
C346  2.2uF/0402/6.3V  [c402-25]
C347  NO POP  [c402-25]
C352  2.2uF/0402/6.3V  [c402-25]
C381  2.2uF/0402/6.3V  [c402-25]
C407  2.2uF/0402/6.3V  [c402-25]
C408  2.2uF/0402/6.3V  [c402-25]
C430  2.2uF/0402/6.3V  [c402-25]
C431  2.2uF/0402/6.3V  [c402-25]
C433  2.2uF/0402/6.3V  [c402-25]
C459  10uF/6.3V  [c603-35x45]
C680  2.2uF/0402/6.3V  [c402-25]
sheet SH72 - PMIC3
C349  47uF/10V  [C1210-70x102]
C350  47uF/10V  [C1210-70x102]
C353  4.7uF 10V  [C805-35X60]
C354  4.7uF 10V  [C805-35X60]
C375  4.7uF 10V  [C805-35X60]
C376  4.7uF 10V  [C805-35X60]
C377  47uF/10V  [C1210-70x102]
C378  47uF/10V  [C1210-70x102]
C379  4.7uF 10V  [C805-35X60]
C410  47uF/10V  [C1210-70x102]
L13  1uH  [ind2-65x90-ihlp1616]
L14  1uH  [ind2-65x90-ihlp1616]
L15  1uH  [ind2-65x90-ihlp1616]
L16  1uH  [ind2-65x90-ihlp1616]
L17  1uH  [ind2-65x90-ihlp1616]
sheet SH73 - PMIC 4
C326  47uF/10V  [C1210-70x102]
C327  47uF/10V  [C1210-70x102]
C328  47uF/10V  [C1210-70x102]
C338  4.7uF 10V  [C805-35X60]
C341  4.7uF 10V  [C805-35X60]
C342  4.7uF 10V  [C805-35X60]
C380  4.7uF 10V  [C805-35X60]
C409  47uF/10V  [C1210-70x102]
C432  4.7uF 10V  [C805-35X60]
C434  100nF/0402/10V  [c402-25]
L9  1uH  [ind2-65x90-ihlp1616]
L10  1uH  [ind2-65x90-ihlp1616]
L11  1uH  [ind2-65x90-ihlp1616]
L18  1uH  [ind2-65x90-ihlp1616]
R192  0  [r402-25]
R193  0  [r402-25]
R566  NO-POP  [r402-25]
R591  0  [r201-6p6spc]
TP42  TP_0  [tp1-18rd8]
U45  PO9039A387IZWSRQ1  [zws169-13p8]  (sections A,B,C,D,E,F)
sheet SH74 - POWER TPS443351DAP
C51  100uF,25V  [c7343-84x118]
C60  330pF  [c603-35x45]
C61  330pF  [c603-35x45]
C62  22uF,25V, x5R  [c1210-70x102]
C63  22uF,25V, x5R  [c1210-70x102]
C71  100uF 10V  [c7343-84x118]
C72  47UF 16V  [c1210-c7343-dual]
C74  100uF 10V  [c7343-84x118]
C76  100pF  [c603-35x45]
C77  47UF 16V  [c1210-c7343-dual]
C78  100pF  [c603-35x45]
C295  4.7uF/25V  [c805-35x60]
C299  .22uF,50V  [c603-35x45]
C300  .22uF,50V  [c603-35x45]
C301  .01uF  [c402-25]
C302  .01uF  [c402-25]
C303  2000pF  [c402-25]
C304  39pf  [c402-25]
C305  .01uF  [c402-25]
C306  .01uF  [c402-25]
C307  2700pF  [c402-25]
C309  56pf  [c402-25]
C314  1000pF  [c402-25]
C683  100uF 10V  [c7343-84x118]
C684  NO-POP  [c1210-70x102]
C689  100uF 10V  [c7343-84x118]
C690  100uF 10V  [c7343-84x118]
L6  2.2uH ( 7443330220)  [choke-power-we-hcc]
L7  8.2uH(744771008 )  [ind2-115x213-12mm]
Q1  CSD18501Q5A  [pwr-q5a-slps319]
Q2  CSD18501Q5A  [pwr-q5a-slps319]
Q3  CSD18501Q5A  [pwr-q5a-slps319]
Q4  CSD18501Q5A  [pwr-q5a-slps319]
R12  0  [r402-25]
R13  0  [r402-25]
R126  10  [r603-35X45]
R127  10  [r603-35X45]
R134  .005 OHM  [r2725-125x250]
R135  0.015  [R2512]
R138  NP  [r402-25]
R140  NP  [r402-25]
R141  NO-POP  [r402-25]
R142  NO-POP  [r402-25]
R143  49.9  [r603-35x45]
R144  49.9K 1%  [r603-35x45]
R145  16K 1%  [r603-35x45]
R146  84.5K 1%  [r603-35x45]
R147  49.9  [r603-35x45]
R450  0  [r402-25]
R451  0  [r402-25]
R453  1.5K  [r603-35x45]
R454  NO-POP  [r402-25]
R455  0  [r402-25]
R456  0  [r402-25]
R457  0  [r402-25]
R461  20K  [r402-25]
R463  0  [r402-25]
R464  15K  [r402-25]
R472  16K 1%  [r603-35x45]
U23  TPS43351QDAPRQ1  [dap38]
sheet SH75 - TPS22965
C318  220pF 50V  [c603-35x45]
C319  NO-POP  [c603-35x45]
R35  0  [r603-35x45]
R473  10K  [r603-35x45]
R474  NO-POP  [r603-35x45]
U92  TPS22965DSG  [dsg8-11x20]
sheet SH76 - ETHERNET 2V5
C18  2.2uF  [c603-35x45]
C19  NP  [c402-25]
C238  10uF  [c603-35x45]
C239  5.6pF  [c402-25]
C705  2.2uF  [c603-35x45]
C708  NO-POP  [c603-35x45]
C709  220pF 50V  [c603-35x45]
R24  4.99K  [r603-35x45]
R346  10.7K  [r603-35x45]
R832  10.7K  [r603-35x45]
R833  10.7K  [r603-35x45]
RJ1  4.7K  [JMP402-25]
RJ2  4.7K  [JMP402-25]
U80  TPS74801  [drc10-11x33]
U145  TPS22965DSG  [dsg8-11x20]
sheet SH77 - TPS51200
C174  10uF  [C1206-40X70]
C179  10pF  [c402-25]
C186  1000pF  [c402-25]
C187  0.001uF  [c402-25]
C188  10uF  [C1206-40X70]
C191  10uF  [C1206-40X70]
C192  10uF  [C1206-40X70]
C201  10uF  [C1206-40X70]
C202  10uF  [C1206-40X70]
C607  0.1uF  [c402-25]
C658  0.1uF  [c402-25]
C659  0.1uF  [c402-25]
Q6  NTA4153N  [SC-75]
Q7  AO3404A(or BSS138)  [SOT23-28X44-GSD]
R282  100K  [r402-25]
R283  10K  [r402-25]
R284  0  [r402-25]
R285  0  [r402-25]
R290  10  [r402-25]
R291  10.0K  [r402-25]
R292  10.0K  [r402-25]
R293  0.025  [R2512]
R803  NP  [r402-25]
R808  0  [r402-25]
R826  0  [r402-25]
R827  10K  [r402-25]
TP64  TEST POINT  [tp1-6040]
TP65  TEST POINT  [tp1-6040]
U64  TPS51200  [drc10-11x33]

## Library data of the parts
EXP_P1 EXP_P3 = J_-_SamTec_QSH020_40pin_2: Part #: 101881-0020R
R283 R480 R827 = R: Part #: 101370-1003R
ZJ1-ZJ4 = TestPoint1_0: Part #: NO-POP
EXP_P2 = J_-_SamTec_QSH060_120pin_2: Part #: 101881-0060R
TP7-TP15 = TestPoint1_0: Part #: TP-18RD8-NO-POP
TP16-TP21 TP24-TP26 TP28-TP36 TP41-TP43 TP66 = TP_0: Part #: TP-18RD8-NO-POP
C100 C434 = C_100nF_0402_6.3V_X5R_0402: Part #: 101587-1100R
C115 C116 = C_12pF_0402_50V_COG_0402: Part #: 101782-1124R
C99 C101-C103 C346 C352 C381 C403 C407 C408 C430 C431 C433 = C_2.2uF_0402_6.3V_X5R_0402: Part #: 103649-0220R
C435 C696 = CAP_NP: Part #: 101587-1100R; Spectrum Part#: 100994-1100
R191 R514 R783 R784 R788 = R_10K_0402_1%_Multi: Part #: R0402-NOPOP
R194 R206 R208-R210 R483 R533 R537 R570 R592 = R_10K_0402_1%_Multi: Part #: R0201-NOPOP
R205 R534 R535 R565 R590 = R_10K_0402_1%_Multi: Part #: 103158-1003R
R207 R549 R591 = R_10K_0402_1%_Multi: Part #: 103158-0001R
R211 = R_10K_0402_1%_Multi: Part #: 103158-1742R
R513 R518 = R_10K_0402_1%_Multi: Part #: 101370-1003R
R516 = R_10K_0402_1%_Multi: Part #: r0201-nopop
R141 R142 R567 R803 = R: Part #: R0402-NOPOP
R588 R589 = R_10K_0402_1%_Multi: Part #: 103158-2002R
R708 R709 = R: Part #: R0201-NOPOP
R12 R13 R284 R285 R710 R808 R826 = R: Part #: 101370-0001R
R782 R809 = R_10K_0402_1%_Multi: Part #: 101370-0001R
R797 = R: Part #: 102145-1742R
SW8 = SW_DIP-2: Part #: 101184-0002R
U101 = SN74AVC2T45DCT: Part #: 102051-0001R
Y4 = Crystal_CM519_CTS407: Part #: 104248-1638R
C339 C343 C347 = C_2.2uF_0402_6.3V_X5R_0402: Part #: C0402-NOPOP
C459 = C_10uF_6.3V_X5R_0603: Distributor ref: 1288201; Part #: 102963-0101R
C680 = CAP_NP_0: Part #: 103649-0220R
C326-C328 C349 C350 C377 C378 C409 C410 = C_10uF_6.3V_X5R_0603: Distributor ref: 1288201; Part #: 103055-0471R
C338 C341 C342 C353 C354 C375 C376 C379 C380 = C_4.7uF_0402_6.3V_X5R_0402: Part #: 101063-0470R
L13 L15 L17 = IND_1.47uH_DFE252012C_R47N: Manufacturer ref: IHLP-1616ABER1R0M11; Part #: 104246-0100R
L11 L14 L16 L18 = IND_0.47uH_DFE252010C_R47N: Manufacturer ref: IHLP-1616ABER1R0M11; Part #: 104246-0100R
C432 = C_2.2uF_0402_6.3V_X5R_0402: Part #: 101063-0470R
L9 L10 = IND_0.47uH_LQM2MPR47NG0: Manufacturer ref: IHLP-1616ABER1R0M11; Part #: 104246-0100R
R192 R193 = R_0_0402_1%_Multi: Part #: 101370-0001R
R566 = R_0_0402_1%_Multi: Part #: R0402-NOPOP
U45 = TPS659038_2: Part #: 104252-0004R-TI
C51 = CAP_POL: Part #: 104700-0102R
C60 C61 = CAP: Part #: 100993-3303R
C62 C63 = CAP_NP: Part #: 104292-0221R
C71 C74 C683 C689 C690 = C_0: Part #: 104290-0102R
C72 C77 = CAP: Part #: 104294-0471R
C76 C78 = CAP: Part #: 100993-1103R
C295 = CAP: Part #: 103751-0470R
C299 C300 = CAP: Part #: 103885-1220R
C301 C302 C305 C306 = CAP: Part #: 101587-1101R
C303 = CAP: Part #: 104291-1202R
C304 = CAP: Part #: 101782-1394R
C307 = CAP: Part #: 102058-1272R
C309 = CAP: Part #: 101782-1564R
C314 = CAP: Part #: 101782-1102R
C684 = CAP
L6 = INDUCTOR: Part #: 104227-0220R
L7 = INDUCTOR: Part #: 104288-0820R
Q1-Q4 = MOSFET_CSD16406Q3_0: Part #: 104283-0001R
R126 R127 = RESISTOR: Part #: 100687-1000R
R134 = RESISTOR: Part #: 104280-0005R
R135 = RESISTOR: Part #: 100830-0015R
R138 R140 R454 = RESISTOR: Part #: R0402-NOPOP
R143 R147 = RESISTOR: Part #: 100642-4990R
R144 = RESISTOR: Part #: 100642-4993R
R145 R472 = RESISTOR: Part #: 102145-1603R
R146 = RESISTOR: Part #: 100642-8453R
R450 R451 R455-R457 R463 = RESISTOR: Part #: 101370-0001R
R453 = RESISTOR: Part #: 100687-1502R
R461 = RESISTOR: Part #: 102145-2003R
R464 = RESISTOR: Part #: 102145-1503R
U23 = TPS43351QDAPRQ1_0: Part #: 104224-0001R
C318 C709 = CAP: Part #: 100993-1223R
C319 C708 = CAP: Part #: C0603-NOPOP
R35 = R: Part #: 100687-0001R
R473 = RESISTOR: Part #: 100687-1003R
R474 = RESISTOR: Part #: R0603-NOPOP
U92 U145 = TPS22965DSG: Part #: 104267-0001R
C18 C705 = CAP_NP: Part #: 101007-0220R
C19 = CAP_NP: Part #: c0402-nopop
C238 = CAP_NP: Part #: 102963-0101R
C239 = Cap_100nF_Cermc_16V_10%_603_3: Part #: 101782-1565R
R24 = R_3: Part #: 100642-4992R
R346 R832 R833 = R_3: Part #: 100642-1073R
RJ1 RJ2 = RJUMP3: Part #: 101370-4702R
U80 = U-TPS78601_AJUST_-_1_3.5A_LDO: Part #: 104335-0001R
C174 C188 C191 C192 C201 C202 = CAP_NP: Part #: 101497-0101R
C179 = CAP_NP: Part #: 101782-1104R
C186 C187 = CAP_NP: Part #: 102058-1102R
C607 C658 C659 = CAP_NP: Part #: 101587-1100R
Q6 = NTA4153N: Part #: 102437-0001R
Q7 = MOSFET_N_0: Part #: 102159-0001R
R282 = R: Part #: 101370-1004R
R290 = R: Part #: 101370-1000R
R291 R292 = R: Part #: 102145-1003R
R293 = R: Part #: 100830-0025R
TP64 TP65 = TEST_POINT: Part #: 100115-0001R
U64 = TPS51200: Part #: 103316-0001R

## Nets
1V8_I2C1_SCL: R708.1 U45.L1(I2C1_SCL_SCK) ; also on sheet 53
1V8_I2C1_SDA: R709.1 U45.L2(I2C1_SDA_SDI) ; also on sheet 53
1V35_DDR: C187.2 C191.2 C201.2 C659.2 R292.2 U64.2(VLDOIN) ; also on sheet 71 73 81
GND: C18.2 C19.2 C51.2 C60.1 C61.1 C62.1 C63.1 C71.2 C72.2 C74.2 C76.1 C77.2 C78.1 C99.1 C100.1 C101.2 C102.1 C103.1 C115.2 C116.2 C174.1 C179.1 C186.1 C187.1 C188.1 C191.1 C192.1 C201.1 C202.1 C238.2 C295.1 C304.1 C305.2 C306.2 C309.1 C314.2 C318.2 C319.2 C326.1 C327.1 C328.1 C338.1 C339.1 C341.1 C342.1 C343.1 C346.1 C347.2 C349.1 C350.1 C352.2 C353.1 C354.1 C375.1 C376.1 C377.1 C378.1 C379.1 C380.1 C381.1 C403.1 C407.1 C408.1 C409.1 C410.1 C430.2 C431.2 C432.1 C433.2 C434.1 C435.2 C459.1 C607.1 C658.1 C659.1 C680.2 C683.2 C684.2 C689.2 C690.2 C696.2 C705.2 C708.2 C709.2 EXP_P1.2 EXP_P1.4 EXP_P1.10 EXP_P1.19 EXP_P1.20 EXP_P1.29 EXP_P1.30 EXP_P1.39 EXP_P1.40 EXP_P1.41(G1) EXP_P1.42(G2) EXP_P1.43(G3) EXP_P1.44(G4) EXP_P2.26 EXP_P2.27 EXP_P2.77 EXP_P2.78 EXP_P2.115 EXP_P2.116 EXP_P2.121(G1) EXP_P2.122(G2) EXP_P2.123(G3) EXP_P2.124(G4) EXP_P2.125(G5) EXP_P2.126(G6) EXP_P2.127(G7) EXP_P2.128(G8) EXP_P2.129(G9) EXP_P2.130(G10) EXP_P2.131(G11) EXP_P2.132(G12) EXP_P3.19 EXP_P3.20 EXP_P3.41(G1) EXP_P3.42(G2) EXP_P3.43(G3) EXP_P3.44(G4) Q3.1(S1) Q3.2(S2) Q3.3(S3) Q4.1(S1) Q4.2(S2) Q4.3(S3) Q6.2(S) Q7.S R24.2 R145.1 R191.2 R205.2 R206.2 R291.1 R455.1 R461.1 R463.1 R464.1 R472.1 R473.2 R483.2 R513.2 R535.2 R565.2 R570.2 R588.2 R589.2 R590.2 R591.2 R592.2 R788.2 R803.1 R809.1 R832.2 R833.2 U23.9(PGNDA) U23.19(AGND.1) U23.23(AGND.2) U23.30(PGNDB) U23.39(PWR_PAD) U45.A1(SUB_GND) U45.A4(REFGND1) U45.A7(GNDANA) U45.A13(SUB_GND) U45.B2(GPADC_IN0) U45.B10(SUB_GND) U45.B11(SUB_GND) U45.C2(GPADC_IN1) U45.C3(GPADC_IN2) U45.C12(SMPS12_FBK_GND) U45.D4(SMPS7_GND_1) U45.D5(SMPS7_GND_2) U45.D6(SUB_GND) U45.D7(SUB_GND) U45.D10(SMPS1_GND_1) U45.E4(SMPS7_GND_3) U45.E7(VAC/ACOK) U45.E8(SUB_GND) U45.E9(SMPS1_GND_2) U45.E10(SMPS1_GND_3) U45.F4(SMPS4_GND_1) U45.F5(AGND.1) U45.F6(SUB_GND) U45.F7(SUB_GND) U45.F9(SMPS2_GND_1) U45.F10(SMPS2_GND_2) U45.G4(SMPS4_GND_2) U45.G5(SMPS4_GND_3) U45.G7(SUB_GND) U45.G10(SMPS2_GND_3) U45.H4(SMPS5_GND_1) U45.H5(SMPS5_GND_2) U45.H6(SUB_GND) U45.H7(SUB_GND) U45.H10(SMPS3_GND_1) U45.J4(SMPS5_GND_3) U45.J6(SUB_GND) U45.J9(SMPS3_GND_2) U45.J10(SMPS3_GND_3) U45.K3(SMPS45_FDBK_GND) U45.L5(SMPS6_GND) U45.L6(SMPS6_GND_1) U45.L7(SMPS9_GND) U45.L8(SMPS9_GND_1) U45.L9(SMPS8_GND_1) U45.L10(SMPS8_GND) U45.M1(SUB_GND) U45.M2(SUB_GND) U45.M12(GND_DIG) U45.M13(AGND.2) U45.N1(SUB_GND) U45.N2(VIO_GND) U45.N13(SUB_GND) U64.4(PGND) U64.8(GND) U64.11(PWRPAD) U80.6(GND) U80.11(PP1) U92.5(GND) U92.9(PWR_PAD) U101.4(GND) U101.5(DIR) U145.5(GND) U145.9(PWR_PAD) ; also on sheet 3 4 5 7 8 9 10 11 13 15 16 17 18 19 20 21 24 25 26 27 28 29 30 31 32 33 34 35 36 37 38 39 40 42 43 46 47 49 50 51 52 53 54 55 56 57 58 71 72 73 74 75 77 79 80 81 84 85 86 87 88 89
VCC_SENSE: R549.2 U45.B3(VCC_SENSE)
VDD_DSPEVE: U45.K2(SMPS45_FDBK) ; also on sheet 39 72 81
VDD_GPU: U45.K6(SMPS6_FBK) ; also on sheet 39 72 81
VDD_IVA: U45.L11(SMPS8_FDBK) ; also on sheet 39 72 81
VDD_MPU: U45.B13(SMPS12_FBK) ; also on sheet 39 72 79 81
VDDS18V: U45.J8(SMPS9_FBK) ; also on sheet 11 35 36 74
VIN[1]A_CLK: EXP_P2.48 ; also on sheet 24
VIN[1]A_D[0]: EXP_P2.40 ; also on sheet 24
VIN[1]A_D[1]: EXP_P2.41 ; also on sheet 24
VIN[1]A_D[2]: EXP_P2.42 ; also on sheet 24
VIN[1]A_D[3]: EXP_P2.43 ; also on sheet 24
VIN[1]A_D[4]: EXP_P2.44 ; also on sheet 24
VIN[1]A_D[5]: EXP_P2.45 ; also on sheet 24
VIN[1]A_D[6]: EXP_P2.46 ; also on sheet 24
VIN[1]A_D[7]: EXP_P2.47 ; also on sheet 24
VIN[1]A_D[8]: EXP_P2.68 ; also on sheet 24
VIN[1]A_D[9]: EXP_P2.67 ; also on sheet 24
VIN[1]A_D[10]: EXP_P2.70 ; also on sheet 24
VIN[1]A_D[11]: EXP_P2.69 ; also on sheet 24
VIN[1]A_D[12]: EXP_P2.72 ; also on sheet 24
VIN[1]A_D[13]: EXP_P2.71 ; also on sheet 24
VIN[1]A_D[14]: EXP_P2.74 ; also on sheet 24
VIN[1]A_D[15]: EXP_P2.73 ; also on sheet 24
VIN[1]A_D[16]: EXP_P2.3 ; also on sheet 24
VIN[1]A_D[17]: EXP_P2.4 ; also on sheet 24
VIN[1]A_D[18]: EXP_P2.5 ; also on sheet 24
VIN[1]A_D[19]: EXP_P2.6 ; also on sheet 24
VIN[1]A_D[20]: EXP_P2.7 ; also on sheet 24
VIN[1]A_D[21]: EXP_P2.8 ; also on sheet 24
VIN[1]A_D[22]: EXP_P2.9 ; also on sheet 24
VIN[1]A_D[23]: EXP_P2.10 ; also on sheet 24
VIN[1]A_DE0: EXP_P2.25 ; also on sheet 24
VIN[1]A_FLD0: EXP_P2.85 ; also on sheet 24
VIN[1]A_HSYNC0: EXP_P2.1 ; also on sheet 24
VIN[1]A_VSYNC0: EXP_P2.2 ; also on sheet 24
VIN[1]B_CLK1: EXP_P2.75 ; also on sheet 24
VIN[2]A_CLK: EXP_P2.61 ; also on sheet 25
VIN[2]A_D[0]: EXP_P2.79 ; also on sheet 25
VIN[2]A_D[1]: EXP_P2.80 ; also on sheet 25
VIN[2]A_D[2]: EXP_P2.81 ; also on sheet 25
VIN[2]A_D[3]: EXP_P2.82 ; also on sheet 25
VIN[2]A_D[4]: EXP_P2.83 ; also on sheet 25
VIN[2]A_D[5]: EXP_P2.84 ; also on sheet 25
VIN[2]A_D[6]: EXP_P2.87 ; also on sheet 25
VIN[2]A_D[7]: EXP_P2.88 ; also on sheet 25
VIN[2]A_D[8]: EXP_P2.89 ; also on sheet 25
VIN[2]A_D[9]: EXP_P2.90 ; also on sheet 25
VIN[2]A_D[10]: EXP_P2.91 ; also on sheet 25
VIN[2]A_D[11]: EXP_P2.92 ; also on sheet 25
VIN[2]A_D[12]: EXP_P2.93 ; also on sheet 25
VIN[2]A_D[13]: EXP_P2.94 ; also on sheet 25
VIN[2]A_D[14]: EXP_P2.95 ; also on sheet 25
VIN[2]A_D[15]: EXP_P2.96 ; also on sheet 25
VIN[2]A_D[16]: EXP_P2.97 ; also on sheet 25
VIN[2]A_D[17]: EXP_P2.98 ; also on sheet 25
VIN[2]A_D[18]: EXP_P2.109 ; also on sheet 25
VIN[2]A_D[19]: EXP_P2.110 ; also on sheet 25
VIN[2]A_D[20]: EXP_P2.111 ; also on sheet 25
VIN[2]A_D[21]: EXP_P2.112 ; also on sheet 25
VIN[2]A_D[22]: EXP_P2.113 ; also on sheet 25
VIN[2]A_D[23]: EXP_P2.114 ; also on sheet 25
VIN[2]A_DE0: EXP_P2.63 ; also on sheet 25
VIN[2]A_HSYNC: EXP_P2.62 ; also on sheet 25
VIN[2]A_VSYNC: EXP_P2.64 ; also on sheet 25
VIN[4]B_CLK1: EXP_P1.37 ; also on sheet 85
VIN[4]B_D[0]: EXP_P1.27 ; also on sheet 85
VIN[4]B_D[1]: EXP_P1.28 ; also on sheet 85
VIN[4]B_D[2]: EXP_P1.25 ; also on sheet 85
VIN[4]B_D[3]: EXP_P1.26 ; also on sheet 85
VIN[4]B_D[4]: EXP_P1.23 ; also on sheet 85
VIN[4]B_D[5]: EXP_P1.24 ; also on sheet 85
VIN[4]B_D[6]: EXP_P1.21 ; also on sheet 85
VIN[4]B_D[7]: EXP_P1.22 ; also on sheet 85
VIN[4]B_HSYNC1: EXP_P1.31 ; also on sheet 85
VIN[4]B_VSYNC1: EXP_P1.32 ; also on sheet 85
VIN[5]A_CLK0: EXP_P1.17 ; also on sheet 87
VIN[5]A_D[8]: EXP_P1.5 ; also on sheet 2
VIN[5]A_D[9]: EXP_P1.6 ; also on sheet 2
VIN[5]A_D[10]: EXP_P1.7 ; also on sheet 2
VIN[5]A_D[11]: EXP_P1.8 ; also on sheet 2
VIN[5]A_D[12]: EXP_P1.9 ; also on sheet 2
VIN[5]A_D[13]: EXP_P1.18 ; also on sheet 2
VIN[5]A_D[14]: EXP_P1.11 ; also on sheet 2
VIN[5]A_D[15]: EXP_P1.12 ; also on sheet 2
VIN[6]A_D[0]: EXP_P2.13 ; also on sheet 86
VIN[6]A_D[1]: EXP_P2.14 ; also on sheet 86
VIN[6]A_D[2]: EXP_P2.15 ; also on sheet 86
VIN[6]A_D[3]: EXP_P2.16 ; also on sheet 86
VIN[6]A_D[7]: EXP_P2.17 ; also on sheet 86
VIN[6]A_D[8]: EXP_P2.18 ; also on sheet 86
VIN[6]A_D[9]: EXP_P2.19 ; also on sheet 86
VIN[6]A_D[10]: EXP_P2.20 ; also on sheet 86
VIN[6]A_D[11]: EXP_P2.21 ; also on sheet 86
VIN[6]A_HSYNC: EXP_P2.11 ; also on sheet 86
VIN[6]A_VSYNC: EXP_P2.12 ; also on sheet 86
VIN_CONN: R453.2 ; also on sheet 80
AIC3106_I2C_0x19: SW8.3(A3) ; also on sheet 55
APP_BD_PORz: EXP_P2.76 ; also on sheet 33
CORE_VDD: U45.B1(SMPS7_FDBK) ; also on sheet 39 72 81
DDR_VREFSTL1: R285.1 ; also on sheet 19 42
DDR_VREFSTL2: R284.1 ; also on sheet 20 46
ENET_1V8: C708.1 U145.7(VOUT.2) U145.8(VOUT.1) ; also on sheet 56 57
EVM_1V8: EXP_P2.55 EXP_P2.56 U145.1(VIN.1) U145.2(VIN.2) ; also on sheet 8 10 26 52 53 74
EVM_2V5: C238.1 C239.1 R346.1 U80.9(VOUT1) U80.10(VOUT2) ; also on sheet 56 57
EVM_3V3: EXP_P2.57 EXP_P2.58 EXP_P2.59 EXP_P2.60 R283.2 R480.1 RJ1.1 RJ2.1 ; also on sheet 3 4 5 7 8 9 10 11 14 15 16 17 18 24 25 26 27 28 29 30 31 32 33 49 50 51 52 53 56 57 58 78 84 85 86 87 88
EVM_3V3_SW: C319.1 U92.7(VOUT.2) U92.8(VOUT.1) ; also on sheet 77 78 81
EVM_5V0: EXP_P2.65 EXP_P2.66 ; also on sheet 3 26 27 29 31 49 54 78
EVM_12V: C51.1 C62.2 C63.2 EXP_P2.49 EXP_P2.50 EXP_P2.51 EXP_P2.52 EXP_P2.53 EXP_P2.54 Q1.5(D1) Q2.5(D1) R141.1 R142.1 U23.38(VIN) ; also on sheet 11 31 80
EVM_DDR_VTT: C188.2 C192.2 C202.2 C658.2 R290.2 R293.1 TP64.1 U64.3(VO)
GA1: R451.2 U23.6(GA1)
GA2: R457.2 U23.8(GA2)
GB1: R450.2 U23.33(GB1)
GB2: R456.2 U23.31(GB2)
GP1[2]: EXP_P1.13 ; also on sheet 26 33
GP1[3]: EXP_P1.14 ; also on sheet 33
GP2[27]: EXP_P2.108 ; also on sheet 14
GP5[0]: EXP_P2.34 ; also on sheet 2
GP5[1]: EXP_P2.36 ; also on sheet 2
GP5[17]: EXP_P2.32 ; also on sheet 12
GP5[22]: EXP_P1.33 ; also on sheet 85
GP5[25]: EXP_P1.35 ; also on sheet 85
GP5[29]: EXP_P1.34 ; also on sheet 85
GP5[30]: EXP_P1.36 ; also on sheet 85
GP5[31]: EXP_P1.38 ; also on sheet 85
GP6[17]: EXP_P1.15 ; also on sheet 2
GP6[20]: EXP_P3.13 ; also on sheet 2
I2C1_SCL: EXP_P2.30 ; also on sheet 9 11 26 53 55 87 88
I2C1_SDA: EXP_P2.28 ; also on sheet 9 11 26 53 55 87 88
I2C2_SCL: EXP_P3.22 ; also on sheet 9 28 29 84
I2C2_SDA: EXP_P3.21 ; also on sheet 9 28 29 84
I2C3_SCL: EXP_P1.1 ; also on sheet 84
I2C3_SDA: EXP_P1.3 ; also on sheet 84
LDO1_OUT: C430.1 U45.C6(LDO1_OUT) ; also on sheet 78
LDO2_OUT: C101.1 U45.B6(LDO2_OUT) ; also on sheet 76
LDO3_OUT: C352.1 U45.K11(LDO3_OUT) ; also on sheet 75
LDO4_OUT: C347.1 R566.1 U45.K12(NC1)
LDO9_OUT: C102.2 U45.A5(LDO9_OUT) ; also on sheet 76
LDOLN_OUT: C103.2 U45.B5(LDOLN_OUT) ; also on sheet 75
LDOUSB_OUT: C433.1 U45.B9(LDOUSB_OUT) ; also on sheet 77
LDOVANA_OUT: C680.1 U45.C8(LDOVANA_OUT)
LT_PMIC_RESET_OUT: R782.1 U101.3(A2)
MCA2_ACLKX: EXP_P2.29 ; also on sheet 86
MCA2_AFSX: EXP_P2.31 ; also on sheet 86
MCA2_AXR0: EXP_P2.37 ; also on sheet 86
MCA2_AXR1: EXP_P2.33 ; also on sheet 86
MCA2_AXR2: EXP_P2.39 ; also on sheet 86
MCA2_AXR3: EXP_P2.35 ; also on sheet 86
MCA2_AXR4: EXP_P2.23 ; also on sheet 86
MCA2_AXR5: EXP_P2.24 ; also on sheet 86
MCA2_AXR6: EXP_P2.22 ; also on sheet 86
MCA2_AXR7: EXP_P2.38 ; also on sheet 86
MCA6_ACLKX: EXP_P2.104 ; also on sheet 86
MCA6_AFSX: EXP_P2.102 ; also on sheet 86
MCA6_AHCLKX: EXP_P2.106 ; also on sheet 86
MCA6_AXR0: EXP_P2.103 ; also on sheet 86
MCA6_AXR1: EXP_P2.105 ; also on sheet 86
MMC3_CLK: EXP_P3.25 ; also on sheet 83
MMC3_CMD: EXP_P3.26 ; also on sheet 83
MMC3_DAT0: EXP_P3.28 ; also on sheet 83
MMC3_DAT1: EXP_P3.30 ; also on sheet 83
MMC3_DAT2: EXP_P3.27 ; also on sheet 83
MMC3_DAT3: EXP_P3.29 ; also on sheet 83
MMC3_DAT4: EXP_P3.32 ; also on sheet 83
MMC3_DAT5: EXP_P3.34 ; also on sheet 83
MMC3_DAT6: EXP_P3.31 ; also on sheet 83
MMC3_DAT7: EXP_P3.33 ; also on sheet 83
OLD_GPMC_nCS0: EXP_P1.16 R480.2
PB_ON: R12.1 R13.1 ; also on sheet 80
PGD_3V3_5V0: R138.1 R140.1 U23.15(PGA) U23.24(PGB) ; also on sheet 79
PHA: C300.1 L6.1 Q1.1(S1) Q1.2(S2) Q1.3(S3) Q3.5(D1) R126.2 U23.7(PHA)
PHB: C299.1 L7.1 Q2.1(S1) Q2.2(S2) Q2.3(S3) Q4.5(D1) R127.2 U23.32(PHB)
PMIC_32K_CLKOUT: U45.M11(CLK32KGO) ; also on sheet 53
PMIC_BOOT0: R518.2 R788.1 SW8.4(A4) U45.L3(BOOT0)
PMIC_BOOT1: R513.1 R514.2 U45.K7(BOOT1)
PMIC_GPIO_0: R205.1 U45.B12(GPIO_0)
PMIC_GPIO_1: R191.1 R567.2 U45.C13(GPIO_1/VBUSDET)
PMIC_GPIO_2: R206.1 R783.1 U45.A12(GPIO_2/REGEN2)
PMIC_GPIO_3: R535.1 U45.H9(GPIO_3)
PMIC_GPIO_5: R565.1 U45.C10(GPIO_5/CLK32KGO)
PMIC_GPIO_7: R534.2 R537.1 U45.G9(GPIO_7/POWERHOLD)
PMIC_INT: U101.2(A1) ; also on sheet 33
PMIC_OFF: R211.1 ; also on sheet 3 33
PMIC_REGEN1: R784.1 TP41.1 U45.F8(REGEN1)
PMIC_REGEN_3V3: R473.1 R474.2 U45.K10(GPIO_4/SYSEN1) U92.3(ON)
PMIC_REGEN_DDR: U45.N11(GPIO_6/SYSEN2) ; also on sheet 71 73
PMIC_RESET_IN: R533.2 U45.K9(RESET_IN) ; also on sheet 79
PMIC_RESET_OUT: R782.2 R783.2 R784.2 ; also on sheet 33
PMIC_VIO: C434.2 C435.1 R192.2 R210.1 R533.1 R566.2 U45.D9(VIO_IN) U101.8(VCCB)
POWERHOLD: R537.2 ; also on sheet 79
PS_EVM_3V3: C18.1 C71.1 C74.1 C174.2 C302.2 C338.2 C339.2 C341.2 C342.2 C343.2 C346.2 C353.2 C354.2 C375.2 C376.2 C379.2 C380.2 C381.2 C408.2 C459.2 C683.1 C689.1 C690.1 C696.1 R134.1 R140.2 R143.2 R193.1 R194.1 R207.1 R208.1 R209.1 R282.2 R474.1 R516.1 R534.1 R549.1 R827.2 RJ1.3 RJ2.3 U23.11(SA2) U45.C4(LDO9_IN) U45.C5(LDOLN_IN) U45.D11(SMPS1_IN_1) U45.D12(SMPS1_IN_2) U45.D13(SMPS1_IN_3) U45.E1(SMPS7_IN_B1_1) U45.E2(SMPS7_IN_B1_2) U45.E3(SMPS7_IN_B1_3) U45.F1(SMPS4_IN_1) U45.F2(SMPS4_IN_2) U45.F3(SMPS4_IN_3) U45.G11(SMPS2_IN_1) U45.G12(SMPS2_IN_2) U45.G13(SMPS2_IN_3) U45.H11(SMPS3_IN_1) U45.H12(SMPS3_IN_2) U45.H13(SMPS3_IN_3) U45.J1(SMPS5_IN_1) U45.J2(SMPS5_IN_2) U45.J3(SMPS5_IN_3) U45.L12(LDO34_IN) U45.L13(LDO34_IN_1) U45.M4(NC6) U45.M6(SMPS6_IN) U45.M8(SMPS9_IN) U45.M9(SMPS8_IN) U45.N3(NC7) U45.N4(NC8) U45.N6(SMPS6_IN_1) U45.N8(SMPS9_IN_1) U45.N9(SMPS8_IN_1) U64.10(VIN) U80.1(IN1) U80.2(IN2) U92.1(VIN.1) U92.2(VIN.2) U101.1(VCCA) ; also on sheet 31 71 72 73 74 75 77 79
PS_EVM_5V0: C72.1 C77.1 C99.2 C301.2 C407.2 C684.1 C705.1 R35.1 R135.1 R138.2 R147.2 U23.28(SB2) U45.A6(LDO12_IN) U45.A9(LDOUSB_IN2) U45.A10(LDO7USB_IN1) U80.4(BIAS) U145.4(VBIAS) ; also on sheet 10 73 78
PWRON: R208.2 R592.1 U45.G8(PWRON)
RPWRON: R194.2 R570.1 U45.C11(RPWRON)
RSTOUTn: R797.1 ; also on sheet 4 7 8 11 29 30 33 51 55
SMPS_1_2_3: C350.2 C378.2 C410.2 L13.1 L15.1 L17.1 ; also on sheet 72 81
SMPS_4_5: C349.2 C377.2 L14.1 L16.1 ; also on sheet 72 81
SMPS_6: C326.2 L11.1 ; also on sheet 72 81
SMPS_7: C409.2 L18.1 ; also on sheet 72 81
SMPS_8: C328.2 L9.1 ; also on sheet 72 81
SMPS_9: C327.2 L10.1 R192.1 ; also on sheet 74
SPI[1]_CS[0]n: EXP_P3.36 ; also on sheet 87
SPI[1]_CS[1]n: EXP_P3.39 R808.2 ; also on sheet 87
SPI[1]_MISO: EXP_P3.37 ; also on sheet 87
SPI[1]_MOSI: EXP_P3.38 ; also on sheet 87
SPI[1]_SCLK: EXP_P3.35 ; also on sheet 87
SPI[2]_CS[0]n: EXP_P3.2 ; also on sheet 84
SPI[2]_MISO: EXP_P3.3 ; also on sheet 84
SPI[2]_MOSI: EXP_P3.4 ; also on sheet 84
SPI[2]_SCLK: EXP_P3.1 ; also on sheet 84
SW1: L17.2 U45.E11(SMPS1_SW_1) U45.E12(SMPS1_SW_2) U45.E13(SMPS1_SW_3)
SW2: L15.2 U45.F11(SMPS2_SW_1) U45.F12(SMPS2_SW_2) U45.F13(SMPS2_SW_3)
SW3: L13.2 U45.J11(SMPS3_SW_1) U45.J12(SMPS3_SW_2) U45.J13(SMPS3_SW_3)
SW4: L16.2 U45.G1(SMPS4_SW_1) U45.G2(SMPS4_SW_2) U45.G3(SMPS4_SW_3)
SW5: L14.2 U45.H1(SMPS5_SW_1) U45.H2(SMPS5_SW_2) U45.H3(SMPS5_SW_3)
SW6: L11.2 U45.M5(SMPS6_SW_1) U45.N5(SMPS6_SW)
SW7: L18.2 U45.D1(SMPS7_SW_1) U45.D2(SMPS7_SW_2) U45.D3(SMPS7_SW_3)
SW8: L9.2 U45.M10(SMPS8_SW) U45.N10(SMPS8_SW_1)
SW9: L10.2 U45.M7(SMPS9_SW) U45.N7(SMPS9_SW_1)
TPS43351_GC2: U23.4(GC2) ; also on sheet 80
VDAC_3V3: R710.1 ; also on sheet 55 77
VRTC_OUT: C431.1 R514.1 R518.1 R567.1 U45.A8(LDOVRTC_OUT) ; also on sheet 76
VTT: R293.2 R826.1 TP65.1 ; also on sheet 44 48
xtal1: C115.1 U45.A3(OSC16MIN) Y4.1(C1A) Y4.3(C2A)
xtal2: C116.1 U45.A2(OSC16MOUT) Y4.2(C1B) Y4.5(C2B)
N17182110: R13.2 R141.2 U23.16(ENA)
N17182418: R12.2 R142.2 U23.17(ENB)
N17213676: R463.2 U23.22(RT)
N17213686: C60.2 R126.1
N17213736: C61.2 R127.1
N17213790: C299.2 U23.34(CBB)
N17213830: C78.2 R145.2 R146.1 U23.27(FBB)
N17213836: C303.2 C304.2 U23.26(COMPB)
N17213838: C301.1 L7.2 R135.2 U23.29(SB1)
N17213987: C295.2 R454.2 U23.35(VREG)
N17214057: Q2.4(G) R450.1
N17214061: R146.2 R147.1
N17214151: C300.2 U23.5(CBA)
N17214195: C76.2 R144.1 R472.2 U23.12(FBA)
N17214201: C307.2 C309.2 U23.13(COMPA)
N17214229: C302.1 L6.2 R134.2 U23.10(SA1)
N17214255: R454.1 R455.2 U23.20(SYNC)
N17214311: C305.1 U23.14(SSA)
N17214457: R453.1 U23.1(VBAT)
N17214562: C314.1 U23.21(DLYAB)
N17214601: Q1.4(G) R451.1
N17214615: C306.1 U23.25(SSB)
N17214651: R143.1 R144.2
N17298856: EXP_P2.86 TP12.1
N17444583: C186.2 R291.2 R292.1 U64.1(REFIN)
N17444631: R282.1 U64.9(PGOOD)
N17444633: C179.2 R290.1 U64.5(VOSNS)
N17444645: C607.2 R284.2 R285.2 U64.6(REFOUT)
N17444649: Q6.1(G) R283.1 R803.2 R808.1 U64.7(EN)
N17514601: C19.1 U80.7(SS)
N17514605: C239.2 R24.1 R346.2 U80.8(FB)
N17514617: R832.1 RJ1.2 U80.5(EN)
N17551426: R209.2 R590.1 U45.D8(VBUS)
N17551447: U45.G6(RESET_OUT) U101.6(B2)
N17551455: C403.2 U45.C1(OSC16MCAP)
N17551519: R207.2 U45.A11(VCC_SENSE2)
N17551551: TP31.1 U45.J5(ENABLE1)
N17551822: R210.2 R589.1 R797.2 TP43.1 U45.E6(NRESWARM)
N17551928: C100.2 U45.B7(VBG)
N17552158: R483.1 R516.2 U45.K8(PWRDOWN)
N17681908: R35.2 U92.4(VBIAS)
N18013683: EXP_P3.23 TP16.1
N18507369: C432.2 R193.2 U45.C7(VCC1)
N19066656: R591.1 TP42.1 U45.B8(SYNC_TO_EXCLOCK)
N20082076: TP30.1 U45.K1(INT) U101.7(B1)
N20246725: EXP_P2.107 TP8.1
N20307647: TP24.1 U45.J7(POWERGOOD)
N20787900: EXP_P2.100 TP14.1
N20789995: EXP_P2.99 TP7.1
N20790716: EXP_P2.101 TP10.1
N20829145: EXP_P3.10 TP29.1
N20830357: EXP_P3.16 TP21.1
N20849521: EXP_P3.9 TP28.1
N20849522: EXP_P3.15 TP20.1
N21629935: R710.2 SW8.2(A2)
N21952019: R809.2 SW8.1(A1)
N23224137: C307.1 R464.2
N23224139: C303.1 R461.2
N23557168: Q7.D R826.2
N23557549: Q6.3(D) Q7.G R827.1
N24067392: C709.1 U145.6(CT)
N24067721: R833.1 RJ2.2 U145.3(ON)
N35662197: TP32.1 U45.N12(VPROG/TESTV)
N39995776: EXP_P3.17 TP18.1
N41867582: EXP_P3.11 TP25.1
N42624965: R211.2 R588.1 U45.E5(NSLEEP)
N42741901: EXP_P2.119 TP9.1
N42741903: EXP_P2.117 TP11.1
N42747561: EXP_P2.118 TP13.1
N42747573: EXP_P2.120 TP15.1
N42946869: EXP_P3.7 TP33.1
N42946871: EXP_P3.5 TP35.1
N43009183: EXP_P3.6 TP36.1
N43033719: EXP_P3.8 TP34.1
N43059537: EXP_P3.18 TP19.1
N43079890: EXP_P3.12 TP26.1
N43079892: EXP_P3.14 TP66.1
N43162645: EXP_P3.24 TP17.1
N45361223: Q3.4(G) R457.1
N45364158: Q4.4(G) R456.1
N46501256: C318.1 U92.6(CT)
N47347830: R709.2 U45.H8(I2C2_SDA_SDO)
N47347885: R708.2 U45.M3(I2C2_SCL_SCE)

Not connected (* = marked no-connect by the designer): EXP_P3 40; U23 2(NC.2) 3(NC.3) 18(NC.18) 36(NC.36) 37(EXTSUP); U45 B4(GPADC_REF) C9(NC4) K4(NC2) K5(NC5) K13(SMPS3_FDBK) L4(NC3); U80 3(PG); Y4 4(NC.4) 6(NC.6); ZJ1 1; ZJ2 1*; ZJ3 1*; ZJ4 1*

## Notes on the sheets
sheet 59
- BLANK
sheet 60
- JAMR2 BOARD MOUNTING HOLES
sheet 62
- APP_BD_PRESENT_DETECTn
sheet 63
- PMIC HAS DUAL FOOTPRINT
  FOR 32678 HERTZ AND 16.384
  MHZ CRYSTAL
- PMIC_VIO IS 1.8 VOLTS
  NOT THIS MEANS TRANSLATORS FOR I2C AND OTHERS
- REV G3
- REV D
- ER20
- REV G2
- BOOT0 low = Vayu sequence
  BOOT0 high PMIC RESET_OUT pulse mode
  BOOT1 = always low.
- ER14
- ER15
- ER15
- ER24
sheet 64
- (NOT BEING USED??)
- The TPS65903x PMIC LDO3 output has a
  current limit of 300 mA.
  If all PHYs are used concurrently (not
  expected in most systems)
  then the current requirement for the
  PHYs can exceed this limit.
  The System use case should be analyzed
  to verify that the power
  is less than 300 mA if LDO3 is used to
  power the PHYs.  If
  greater than 300 mA is required,
  contact your TI Representative
  to identify an alternate
  implementation.
- ER39
- ER38
sheet 65
- REMOTE SENSING
- REMOTE SENSING
- NOTE INDUCTORS HAVE AUTOMOTIVE AND
  COMMERICAL PART NUMBERS ONE APPLIED AT
  THIS TIME
- REV D
- FOR REPACKAGED TWL PART USE 22uF
  FOR  PRODUCTION PART USE 47uF CAPS
  ON ALL SMPS OUTPUTS C1210
  FOOTPRINT
- REV D
- FOR 3 PHASE FEEDBACK LEFT FLOATING
- REV D
- REMOTE SENSING
- REMOTE SENSING
- REV D
- REV D
sheet 66
- NOTE INDUCTORS HAVE AUTOMOTIVE AND
  COMMERICAL PART NUMBERS ONE APPLIED AT
  THIS TIME
- REMOTE SENSING
- REV D
- FOR REPACKAGED TWL PART USE 22uF FOR
  PRODUCTION PART USE 47uF CAPS ON ALL SMPS
  OUTPUTS
- REMOTE SENSING
- REV D
- REMOTE SENSING
- REV D
- REMOTE SENSING
- REV D
- REV D
sheet 67
- POSSIBLE HIGHER VOLTAGE RANGE ON C62, CHANGE FOOTPRINT TO 1210.
- ER51
- REV D
- 10TPB100ML
- 10 Volts
- Less than ESR 35m-ohm
- POSSIBLE HIGHER VOLTAGE RANGE ON C63
- Fsw = 400KHZ
- 10 Volts
- Less than ESR 35m-ohm
- REV D
- GRM32ER61A476KE20L (1210-10V)
  T525D476M016ATE035 (7343-16V)
- 100uF total
- ER27
sheet 68
- 1.2 volt input
- PMIC TRI-STATES GPIO ON
  STARTUP SO KEEP THE
  SUPPLY DISABLED UNTIL
  DRIVEN.
sheet 69
- REV D
- VOUT = 0.8 * ( 1+(RTOP/RBOTTOM) )
- 2.5 = 0.8 * ( 1+(RTOP/RBOTTOM ))
- 2.5 = 0.8 * ( 1+(RTOP/4.99K ))
- 3.125 =  ( 1+(RTOP/4.99K ))
- 2.125 =  (RTOP/4.99K )
- ER43
- 10.6K =  RTOP
- ER47
sheet 70
- REV G
- ER18
- REV G
- AO3404A -RDSON ~ 35mOHM
- TURN ON ~1.2v
